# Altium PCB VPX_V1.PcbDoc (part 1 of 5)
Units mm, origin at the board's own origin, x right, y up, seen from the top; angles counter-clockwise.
Board outline 157.76 x 100.08 mm, 10 copper layers (Top Layer (PADS/SIG), Layer 2 (GND), Layer 3 (SIG), Layer 4 (SIG), Layer 5 (GND), Layer 6 (PWR), Layer 7 (GND), Layer 8 (SIG/PWR), Layer 9 (GND), Bottom Layer (PAD/SIG)), stack 1.614 mm thick; 383 components, 223 nets, 1313 pads, 1223 vias.
Unrouted connection lines stored in the file: 3.
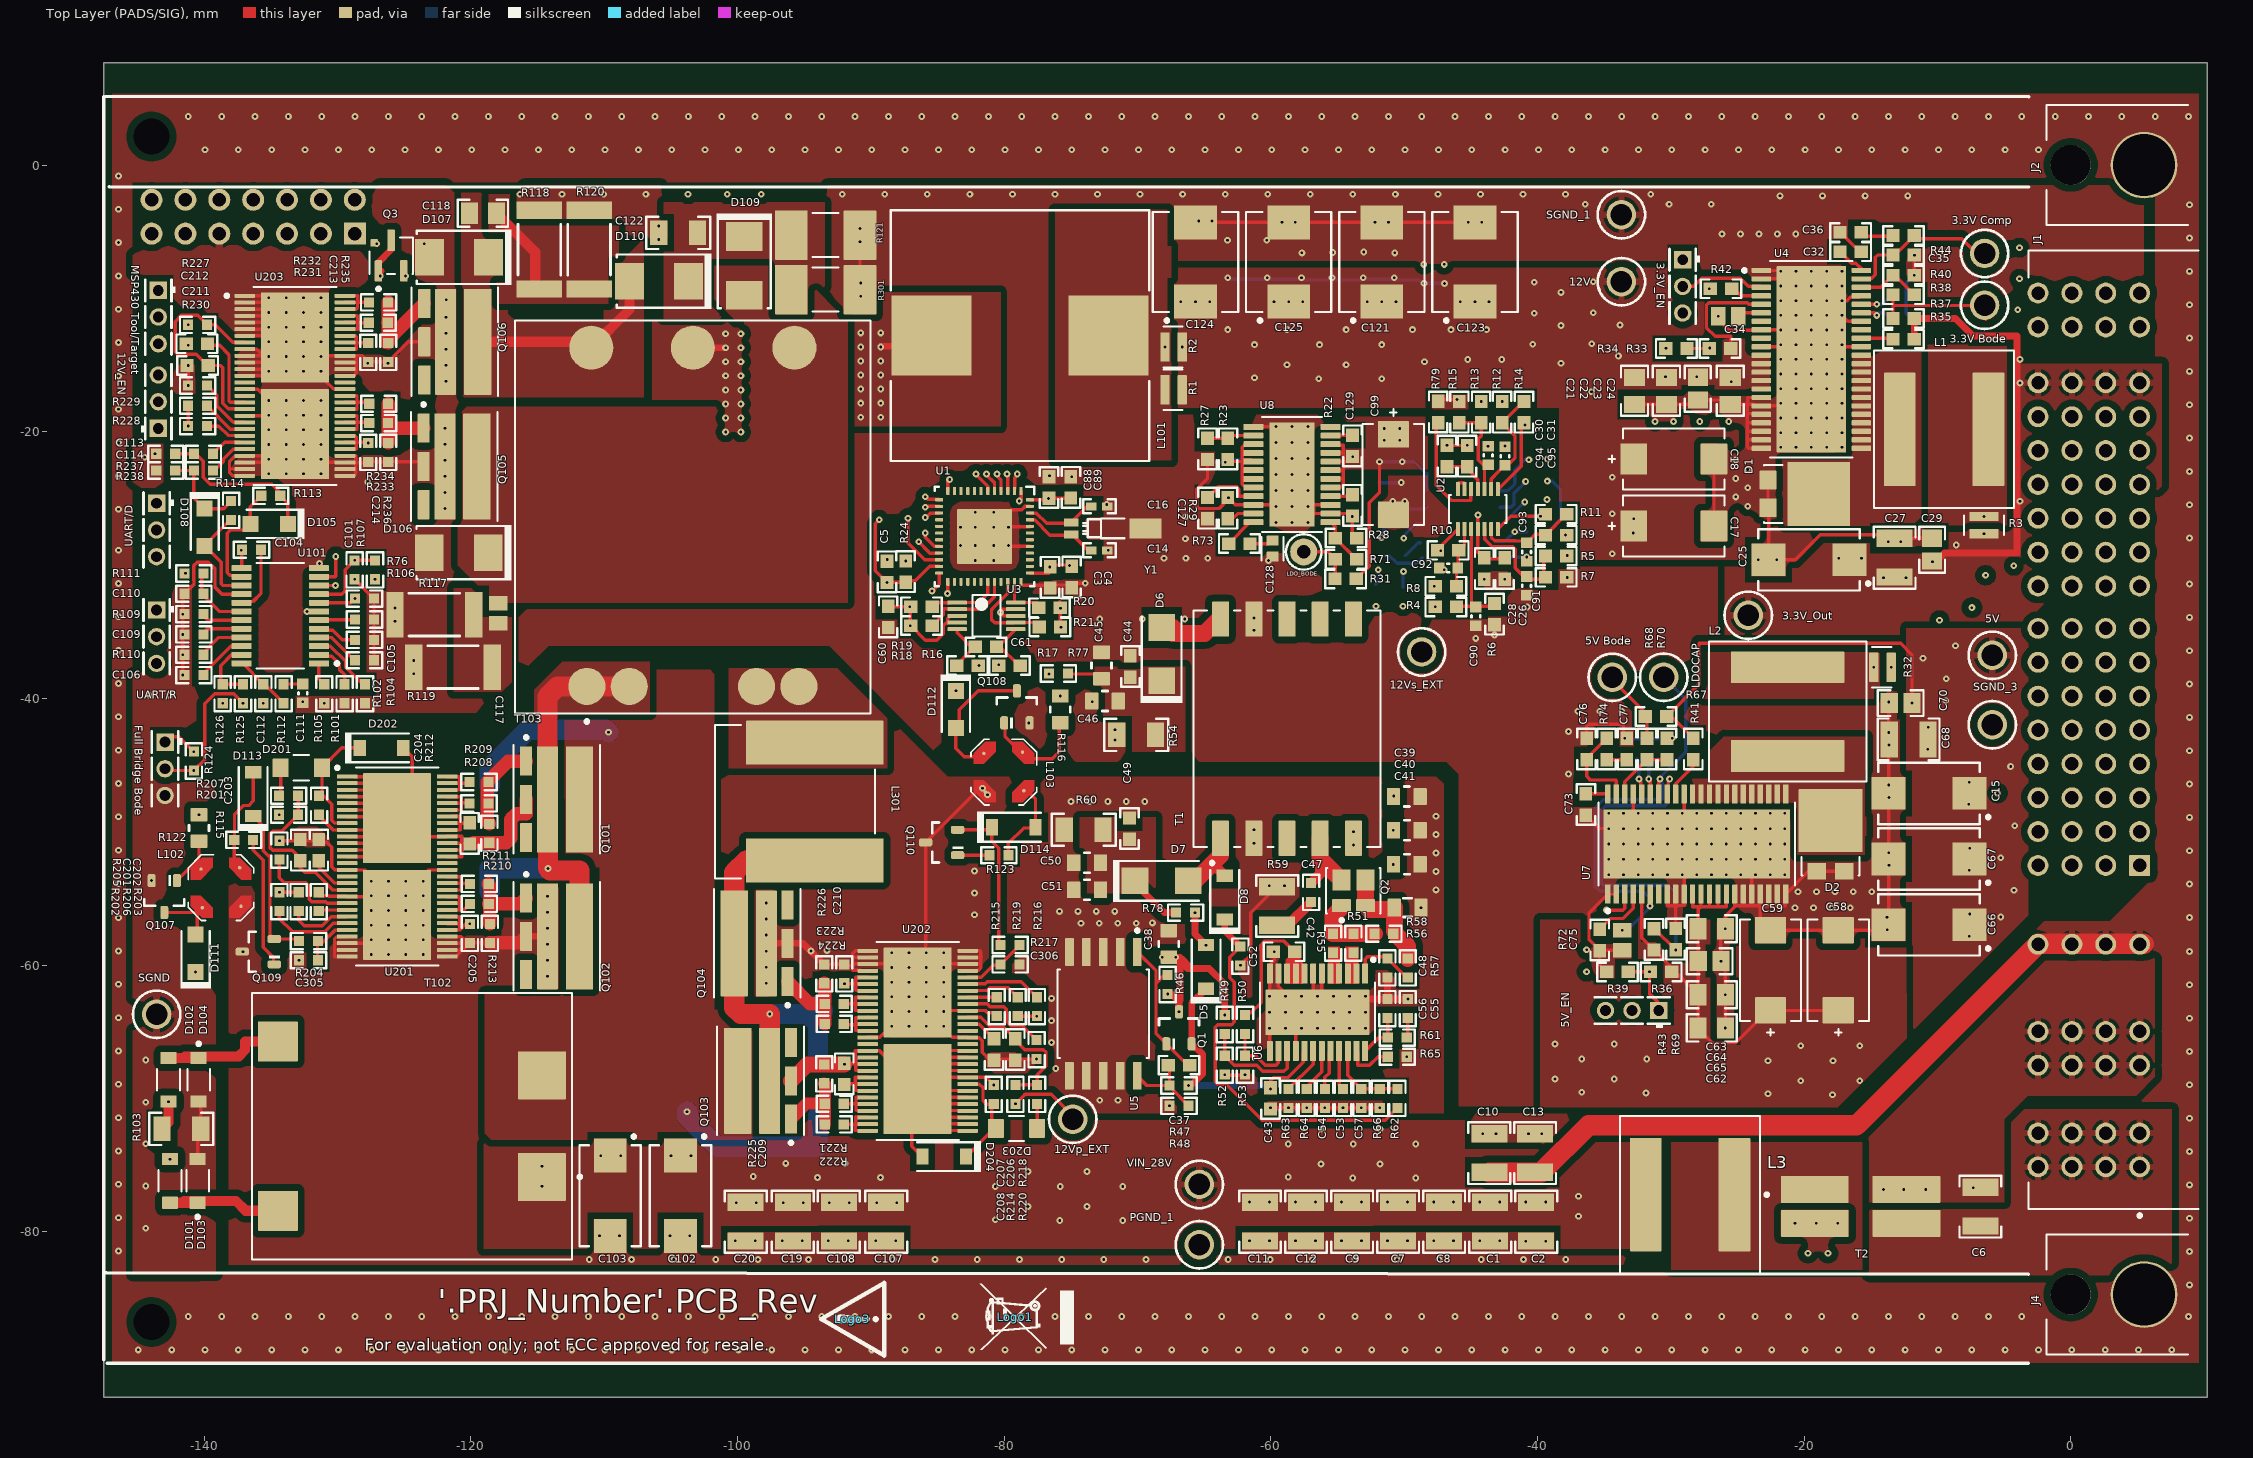
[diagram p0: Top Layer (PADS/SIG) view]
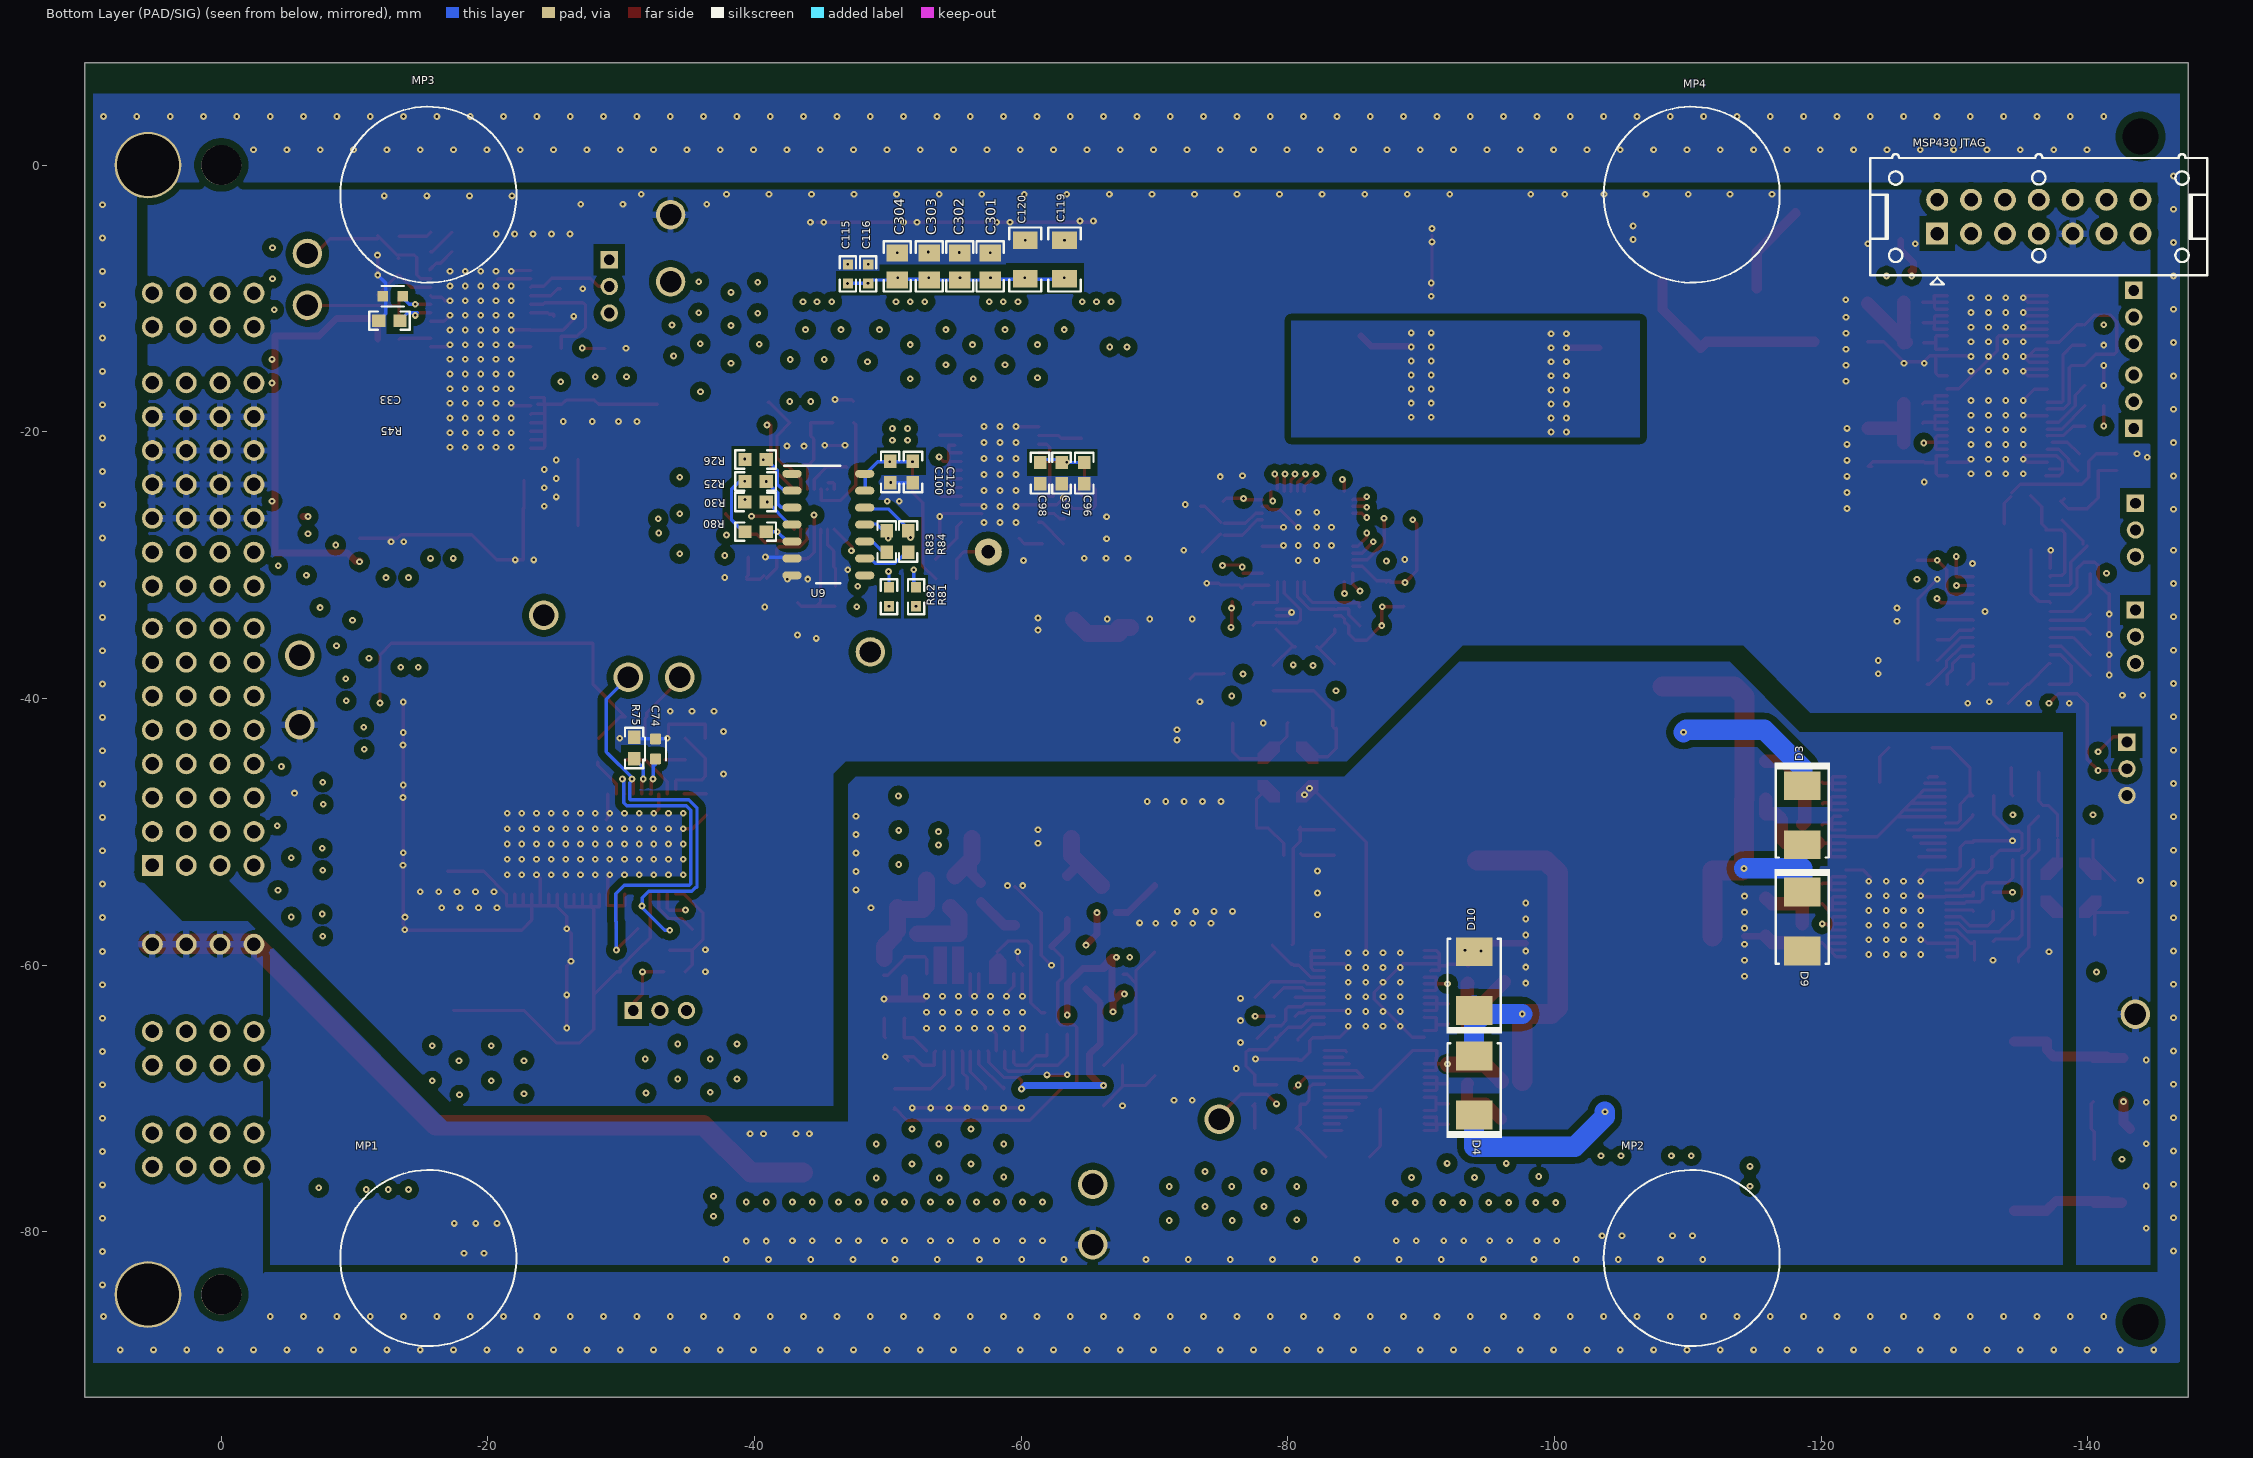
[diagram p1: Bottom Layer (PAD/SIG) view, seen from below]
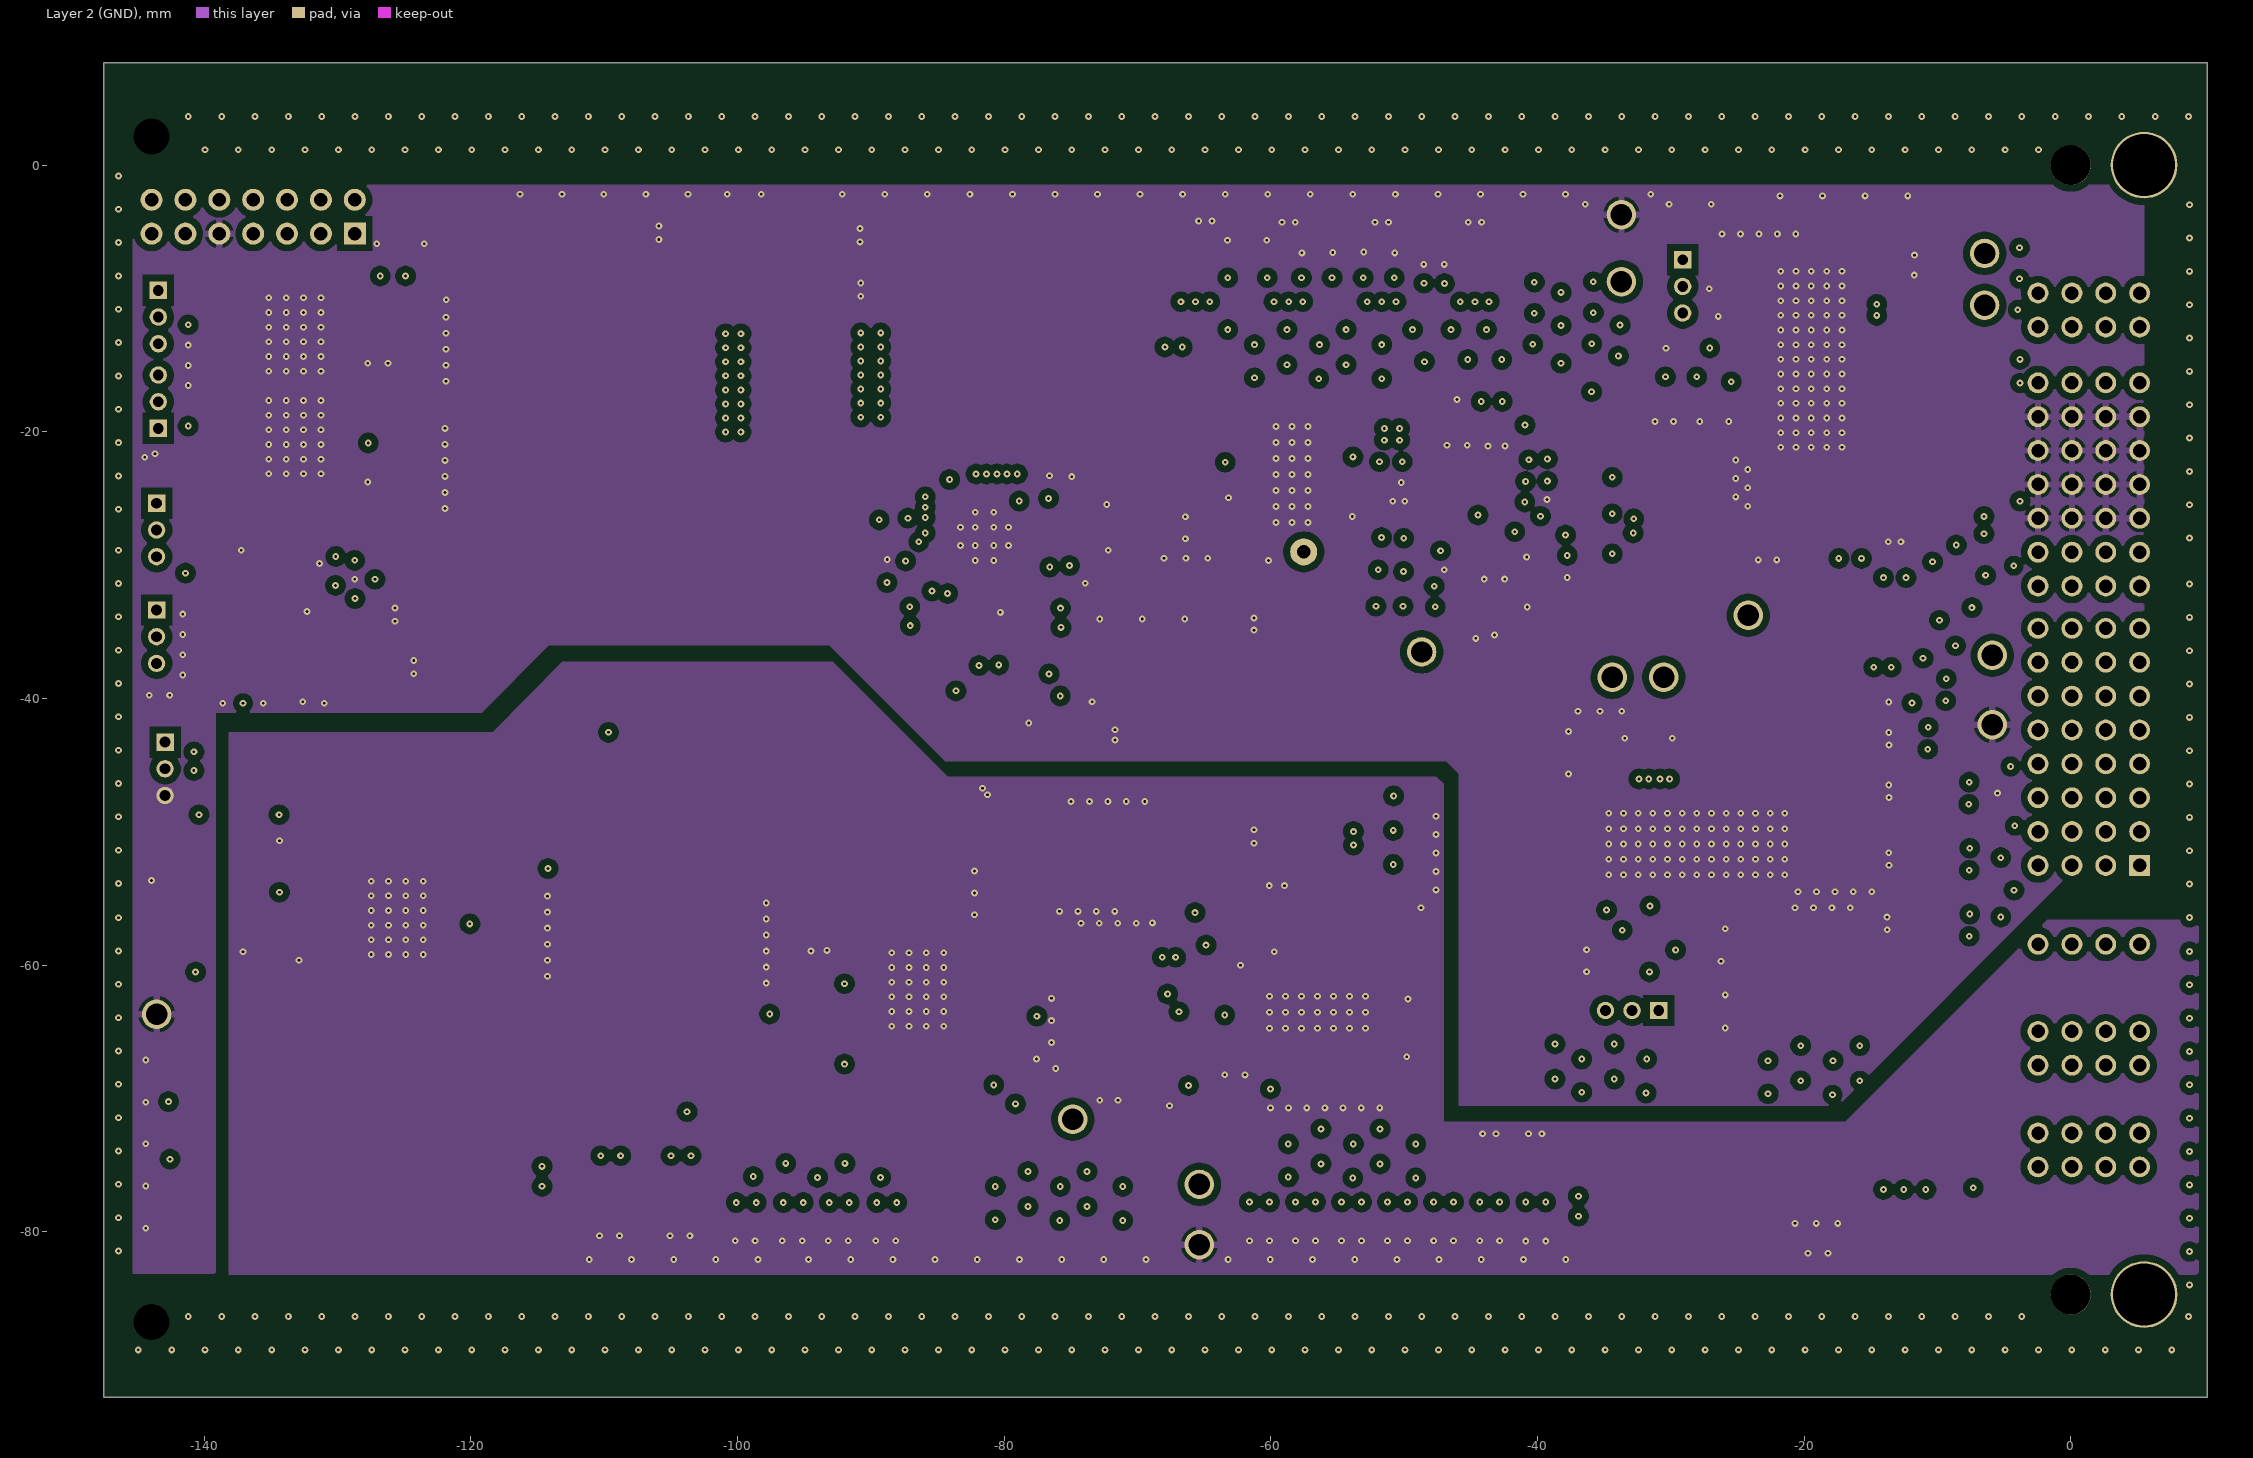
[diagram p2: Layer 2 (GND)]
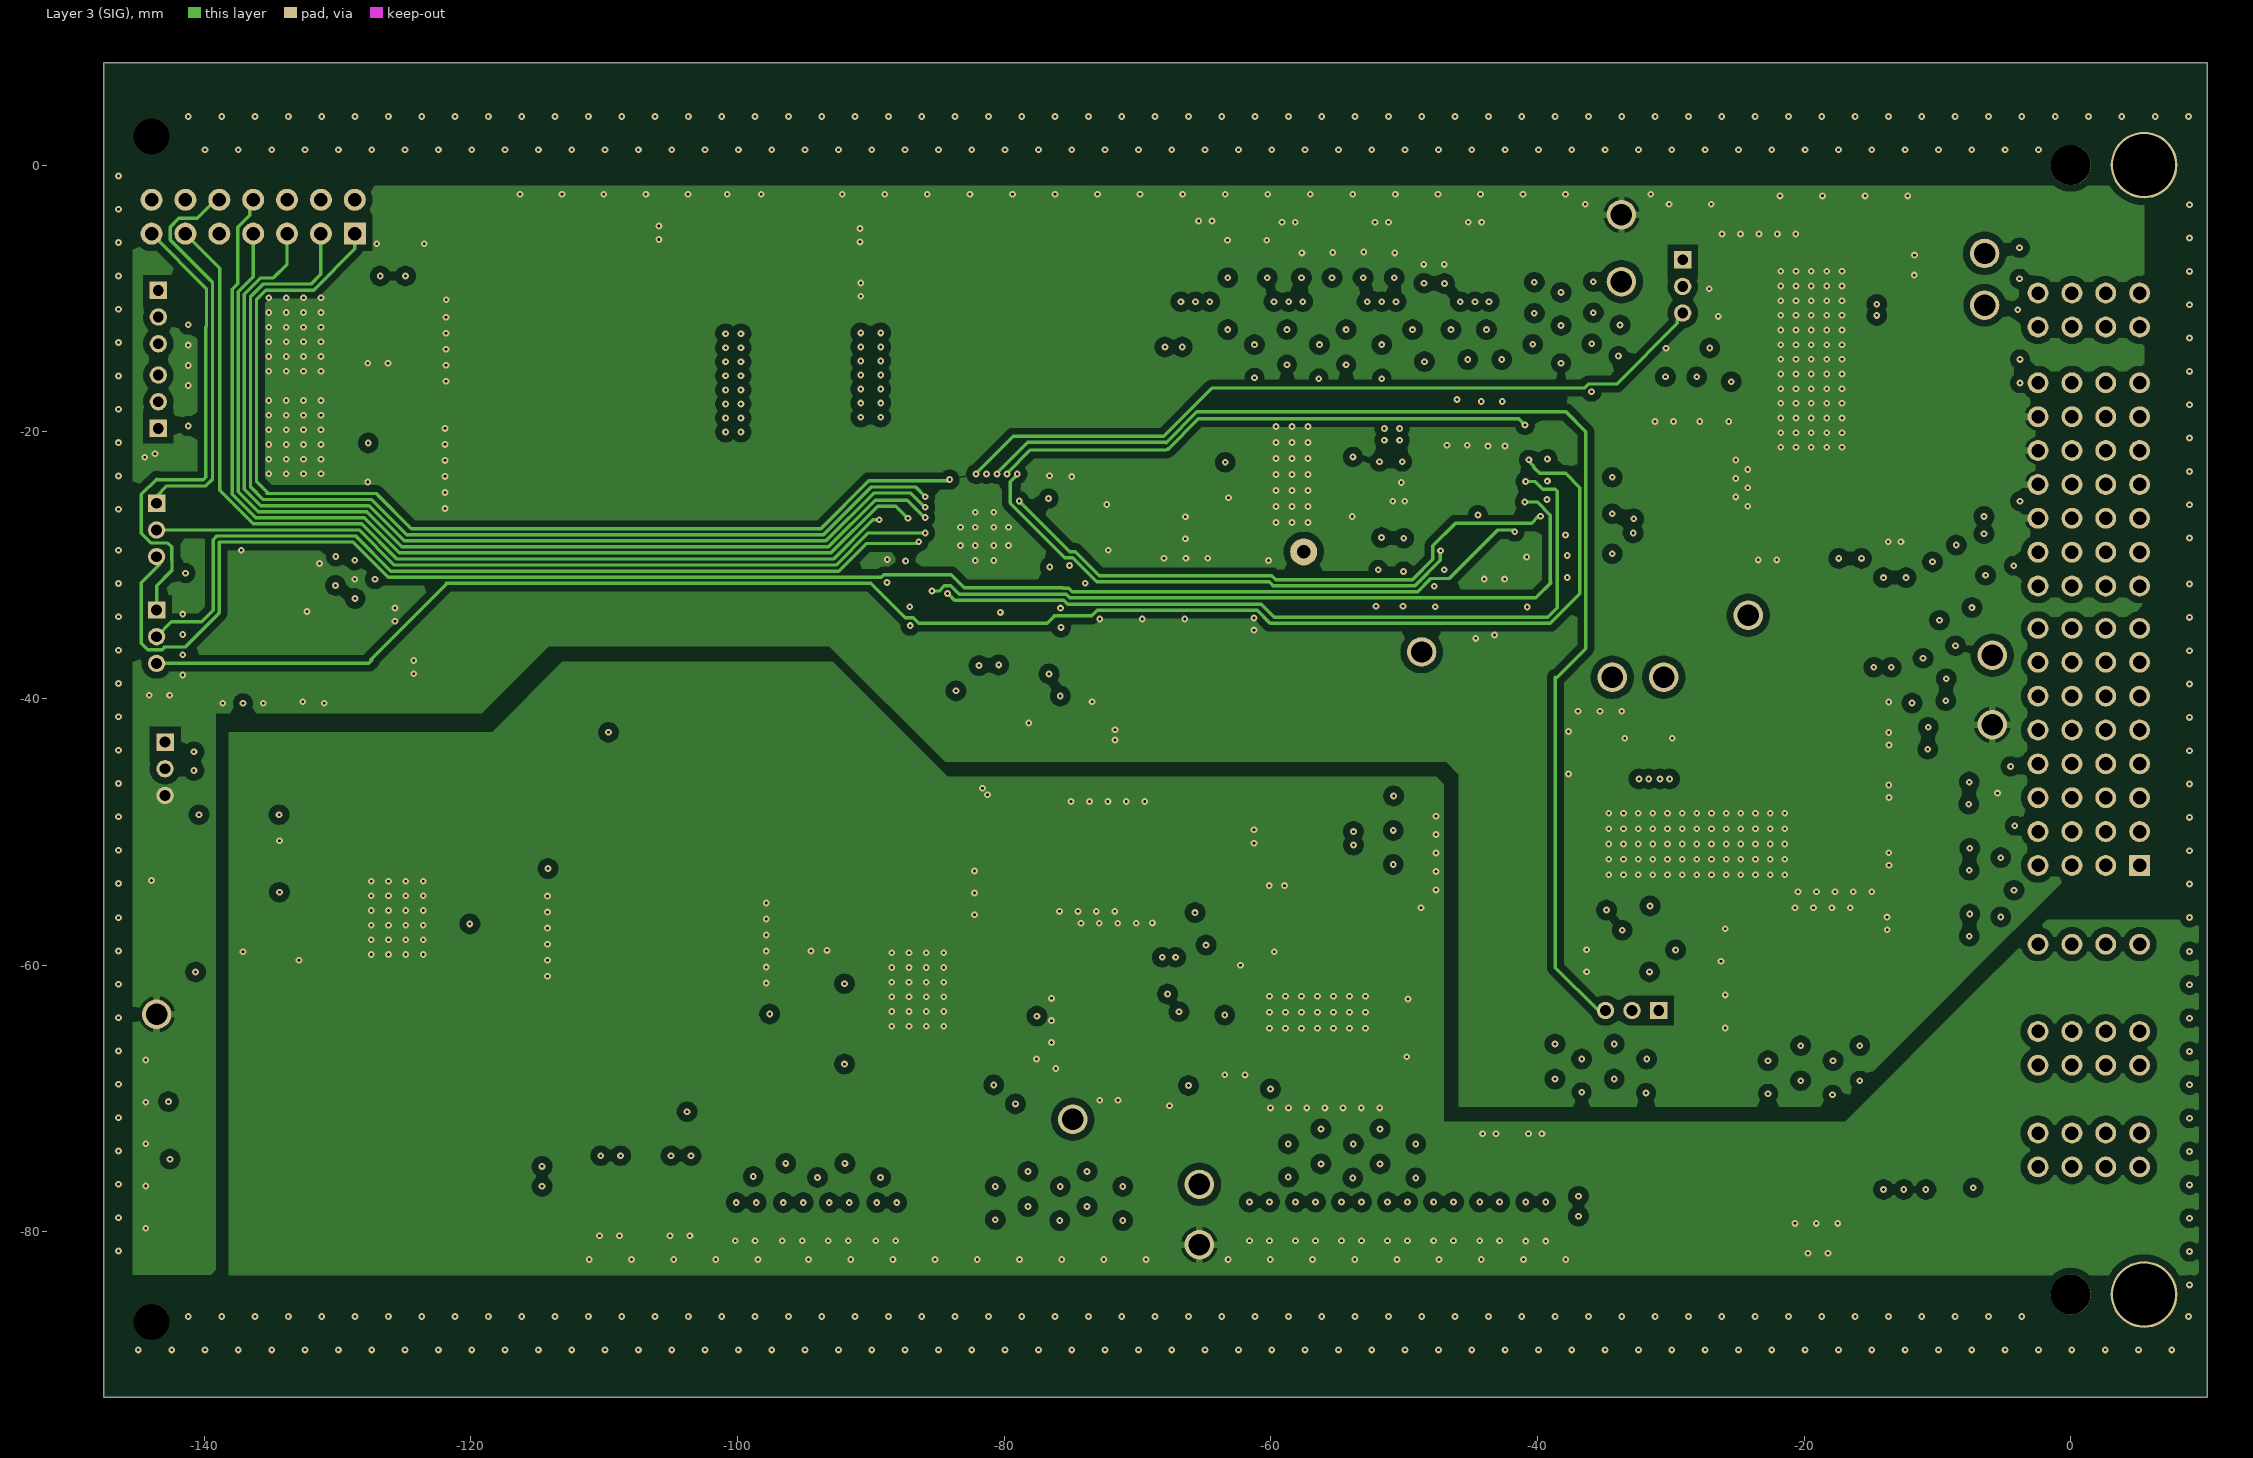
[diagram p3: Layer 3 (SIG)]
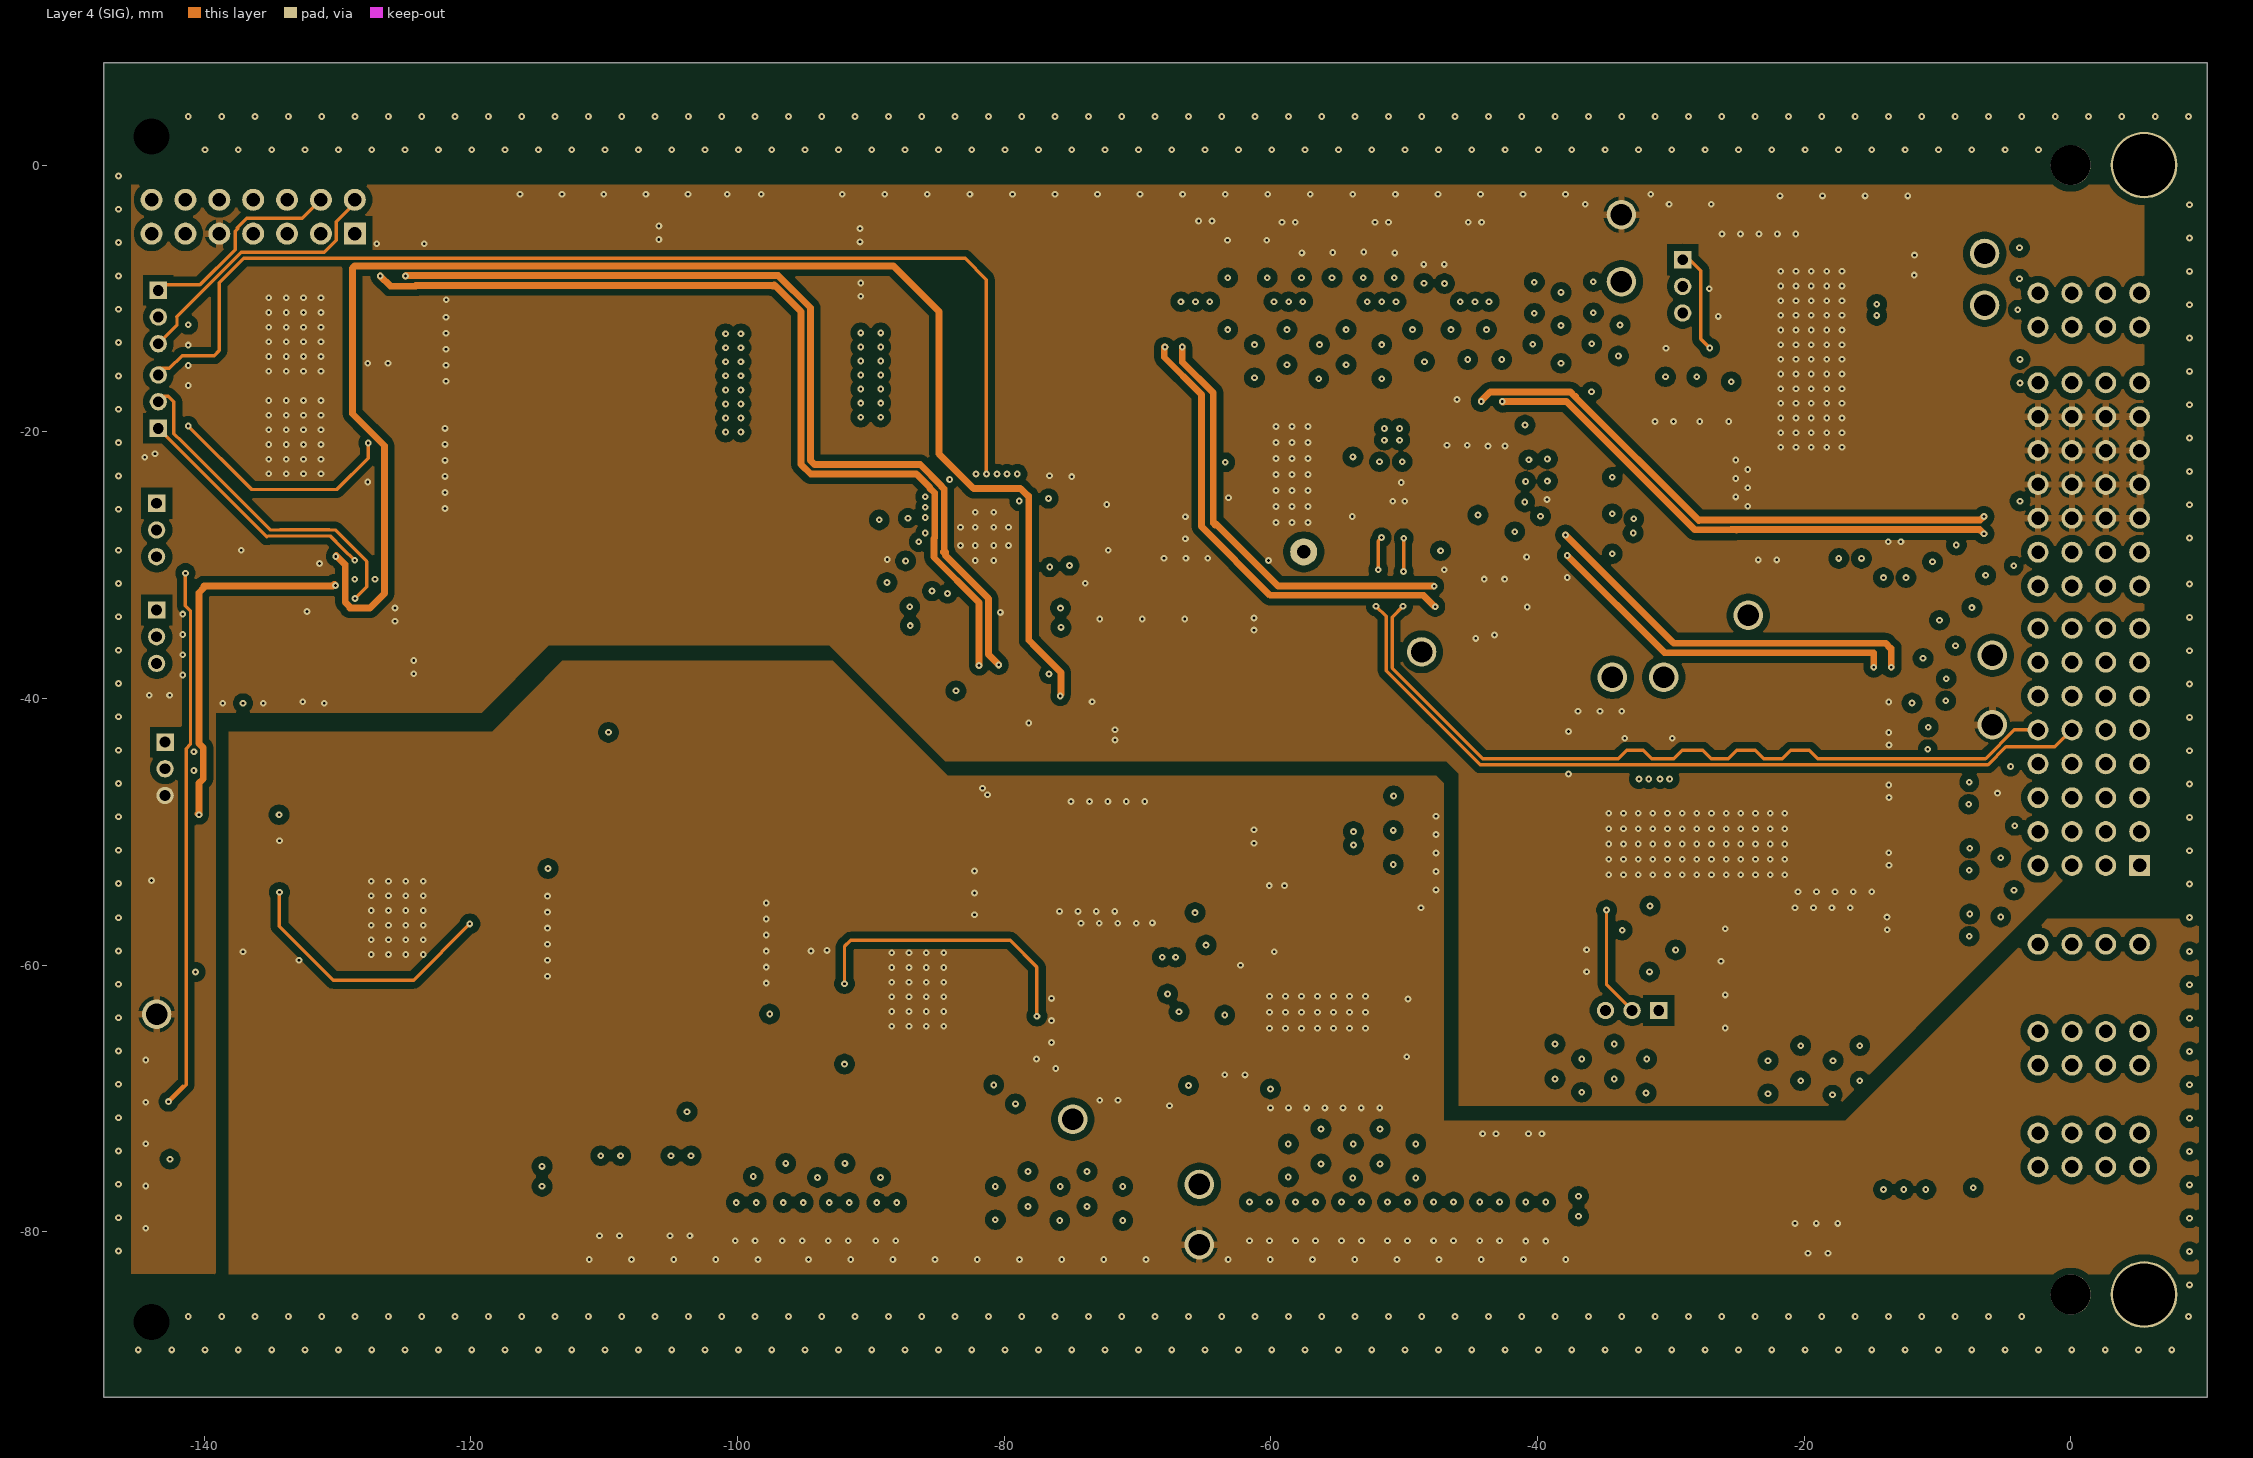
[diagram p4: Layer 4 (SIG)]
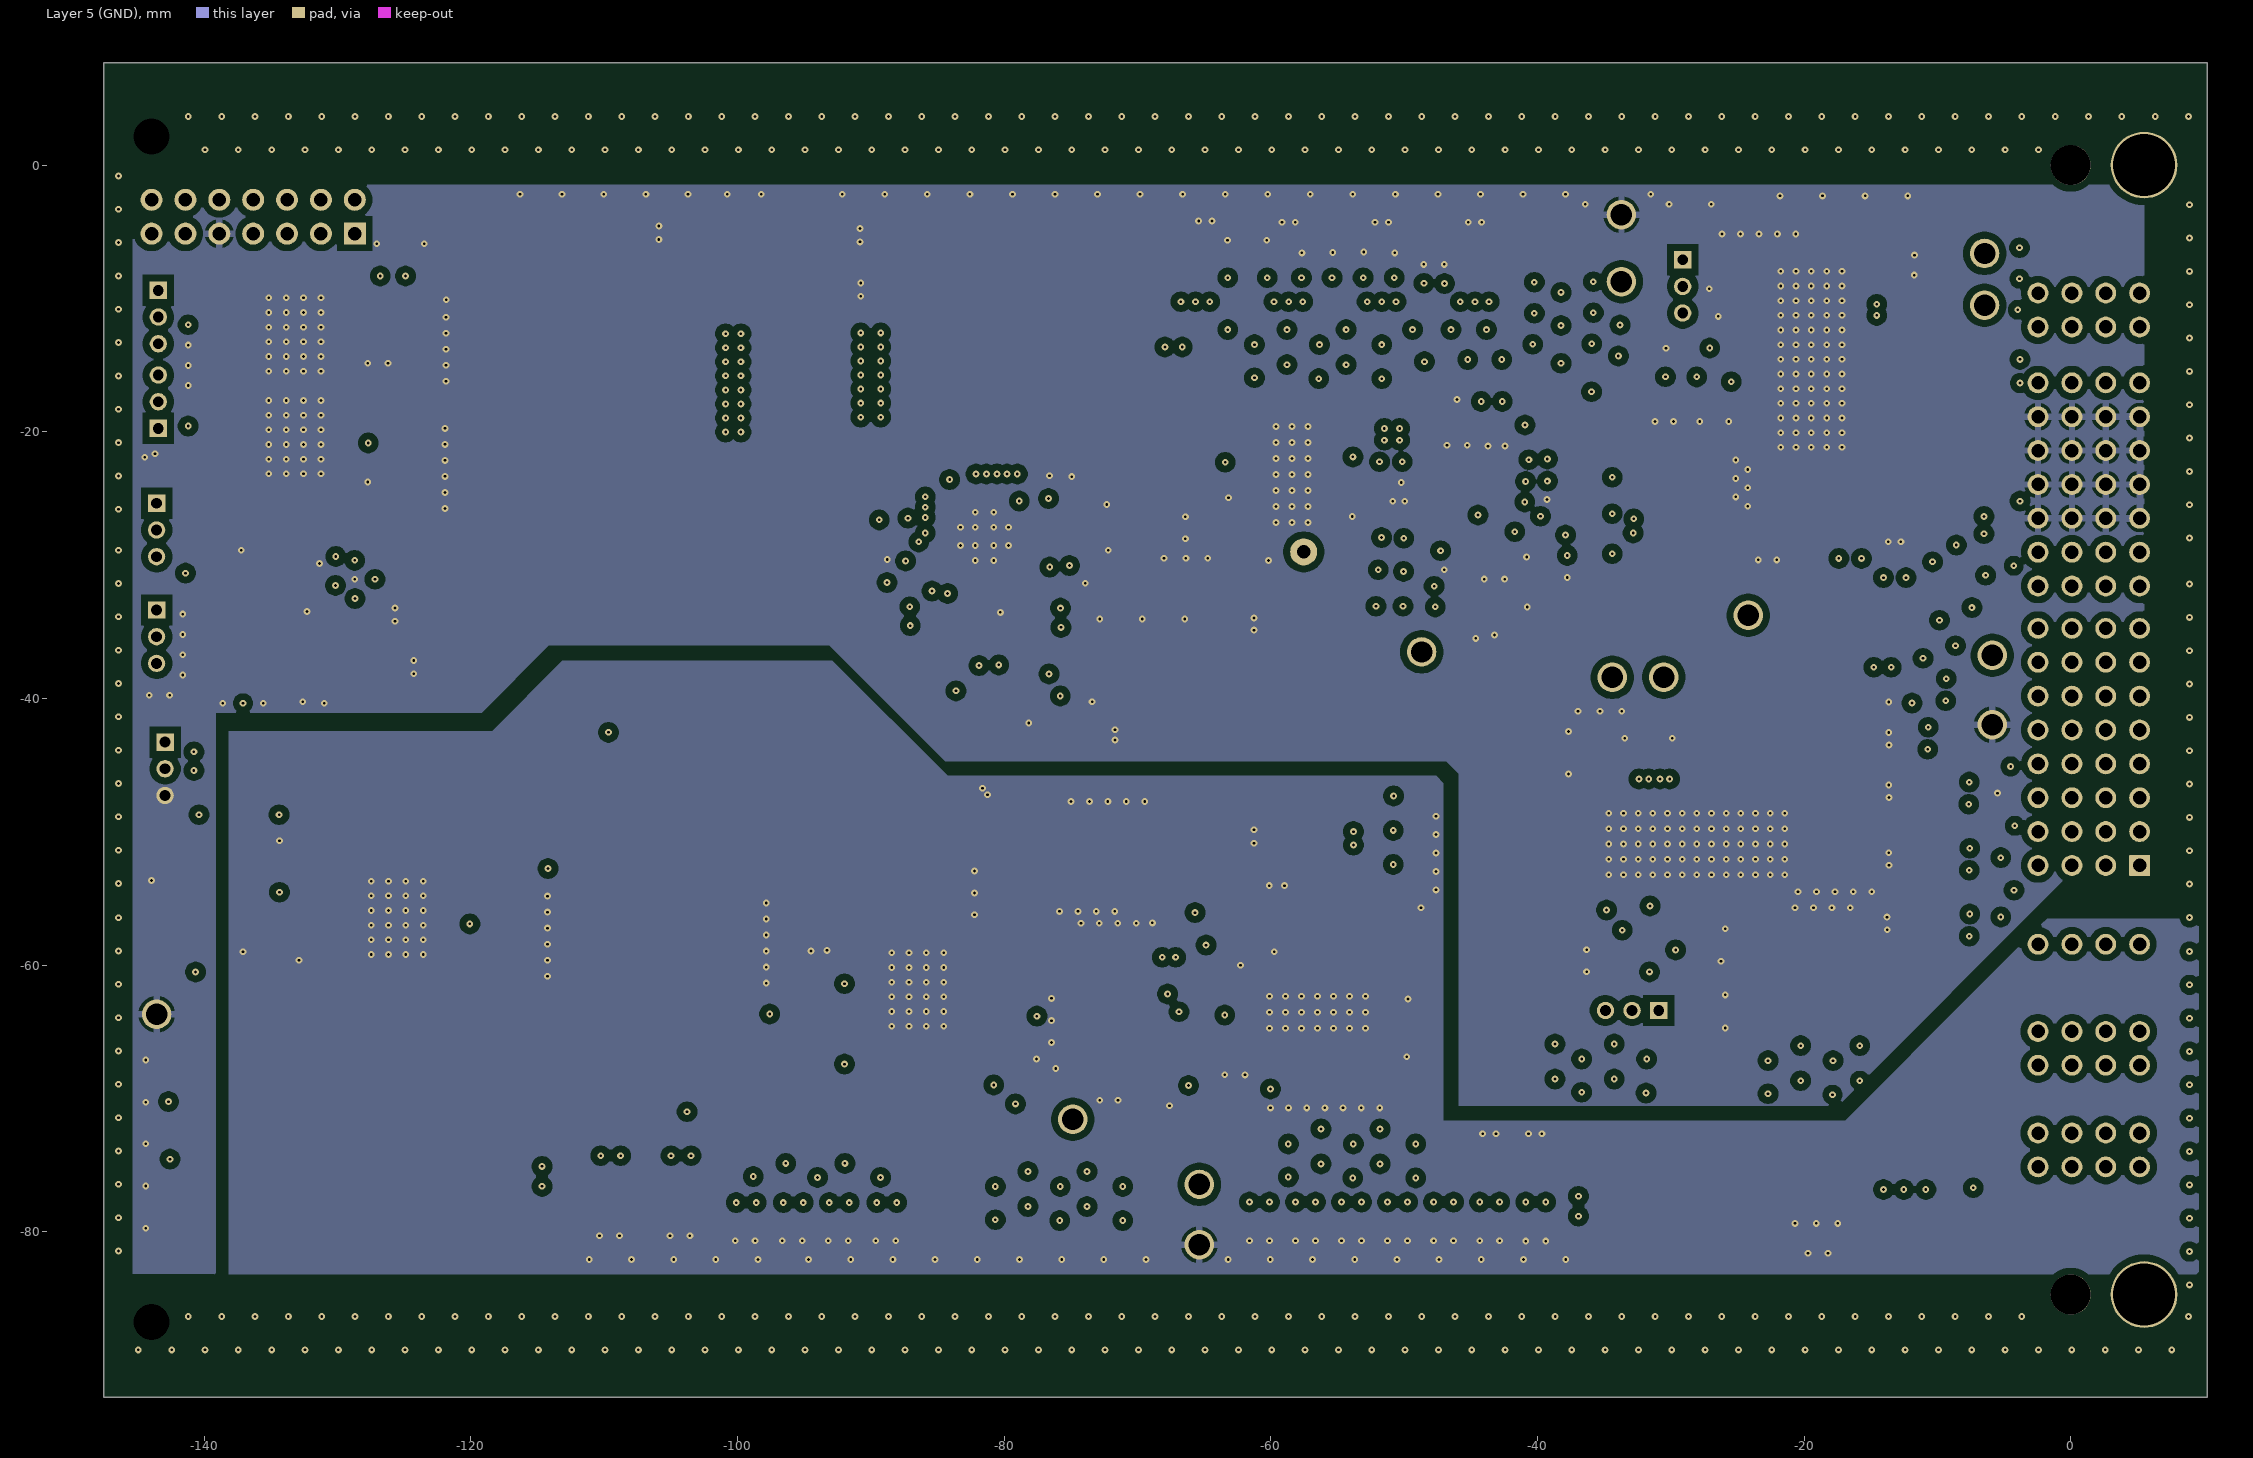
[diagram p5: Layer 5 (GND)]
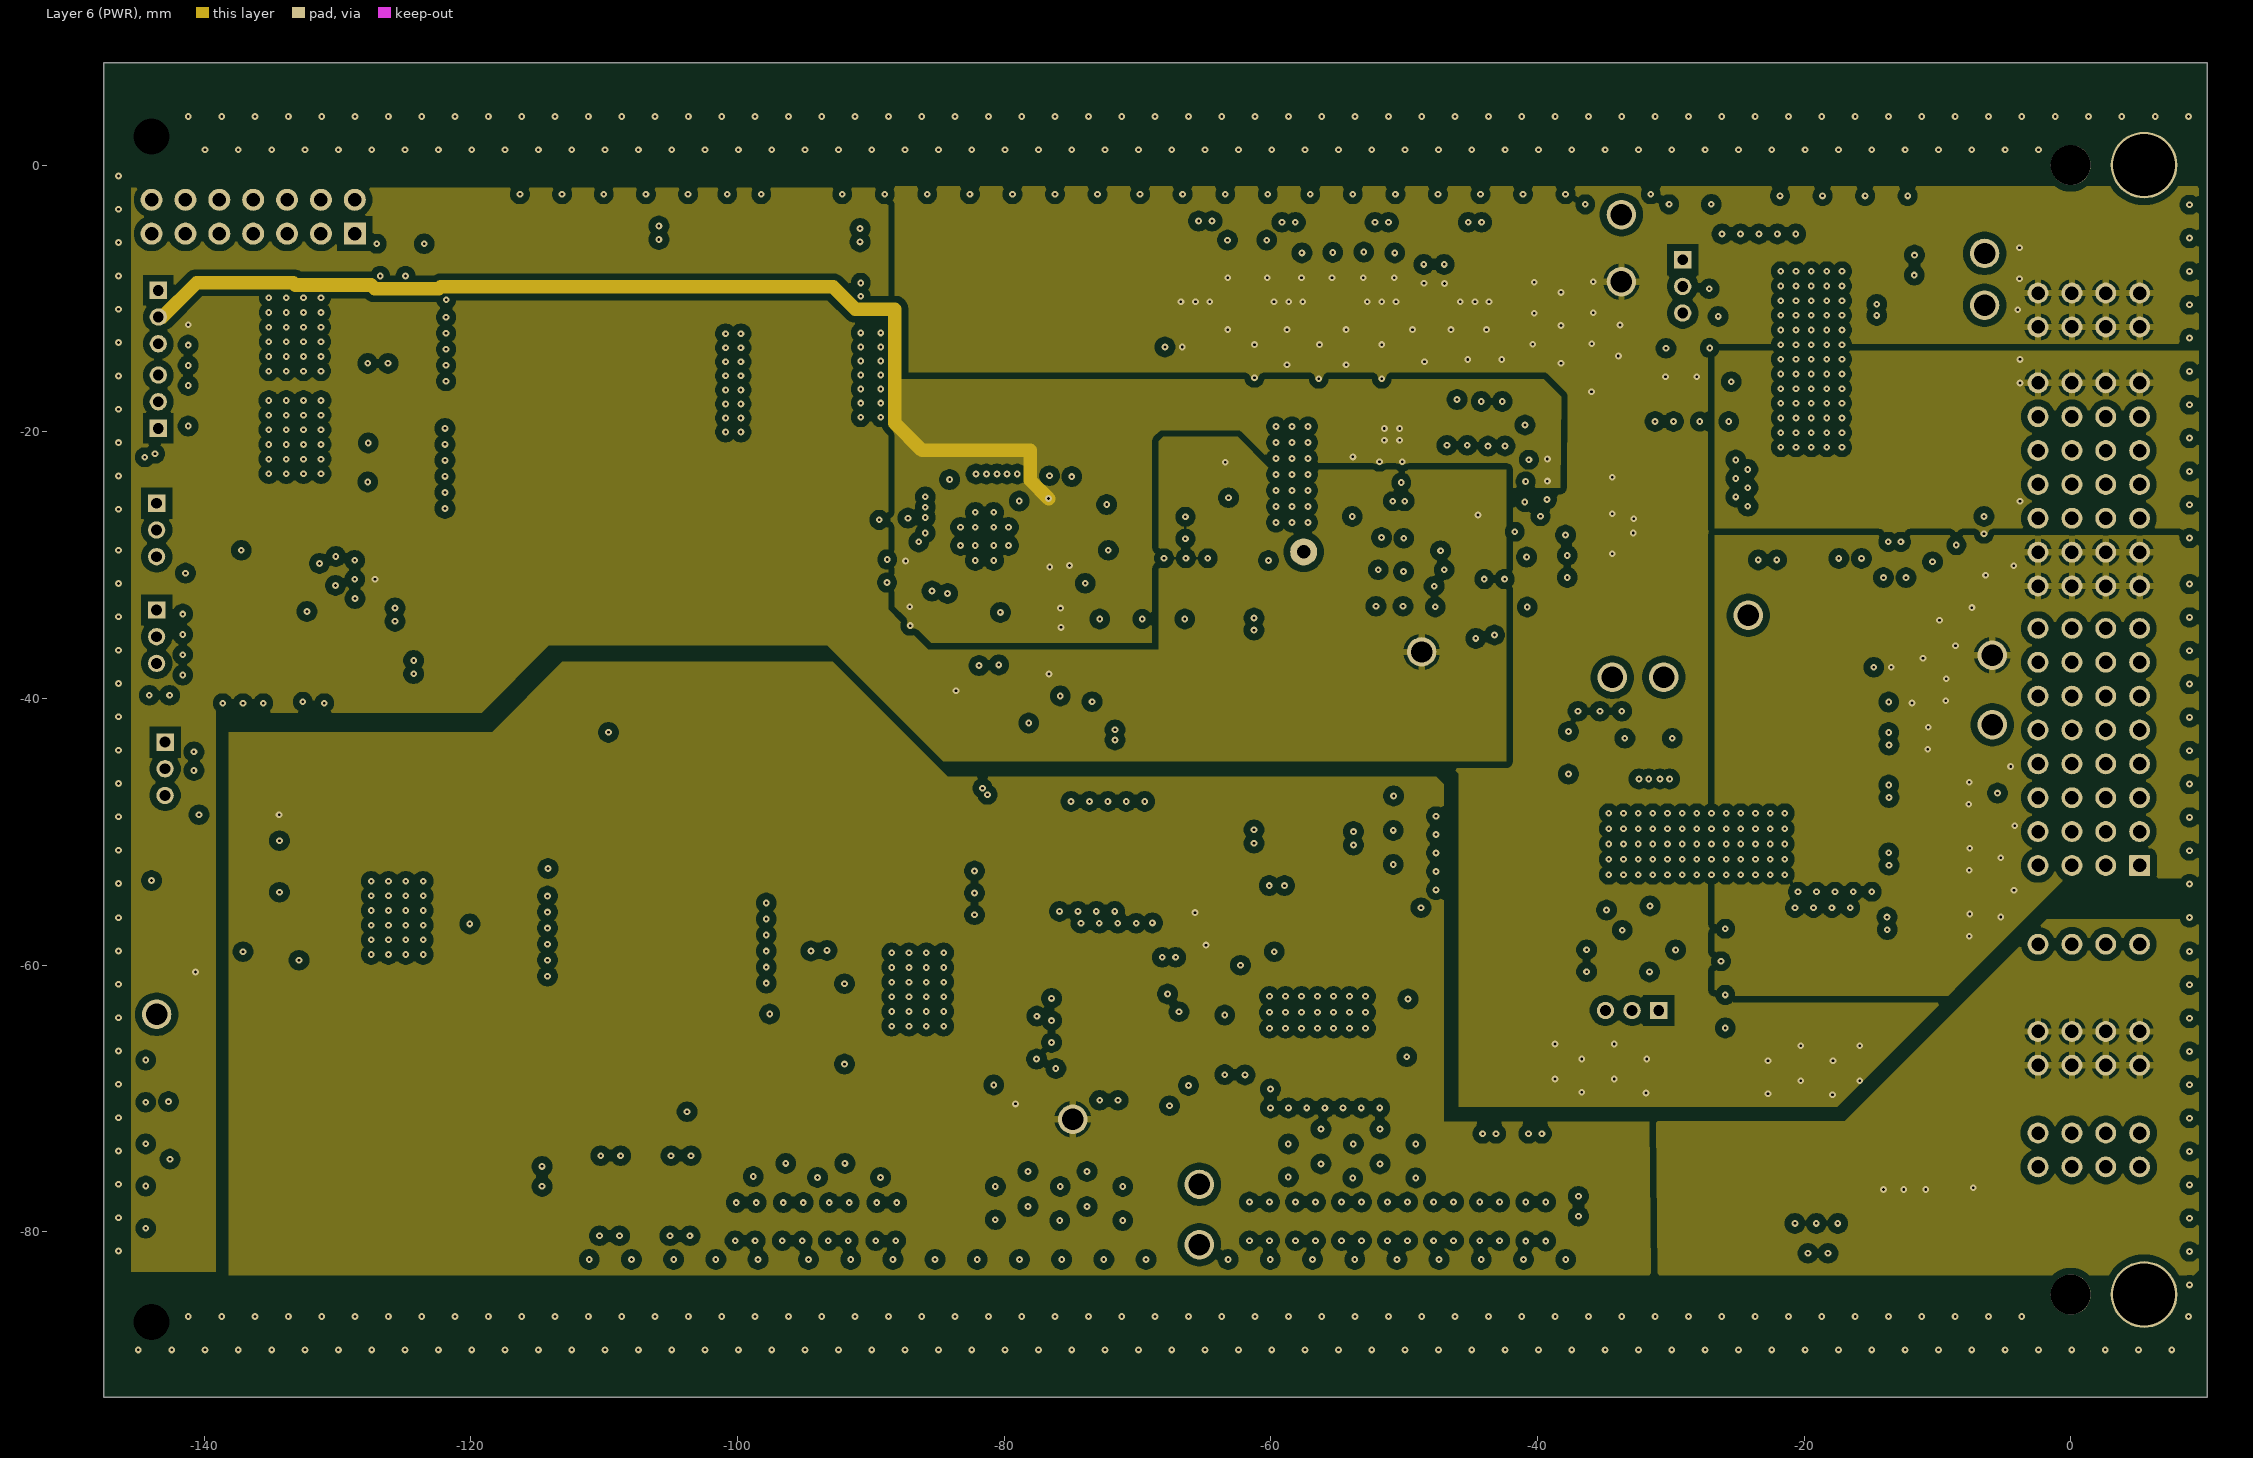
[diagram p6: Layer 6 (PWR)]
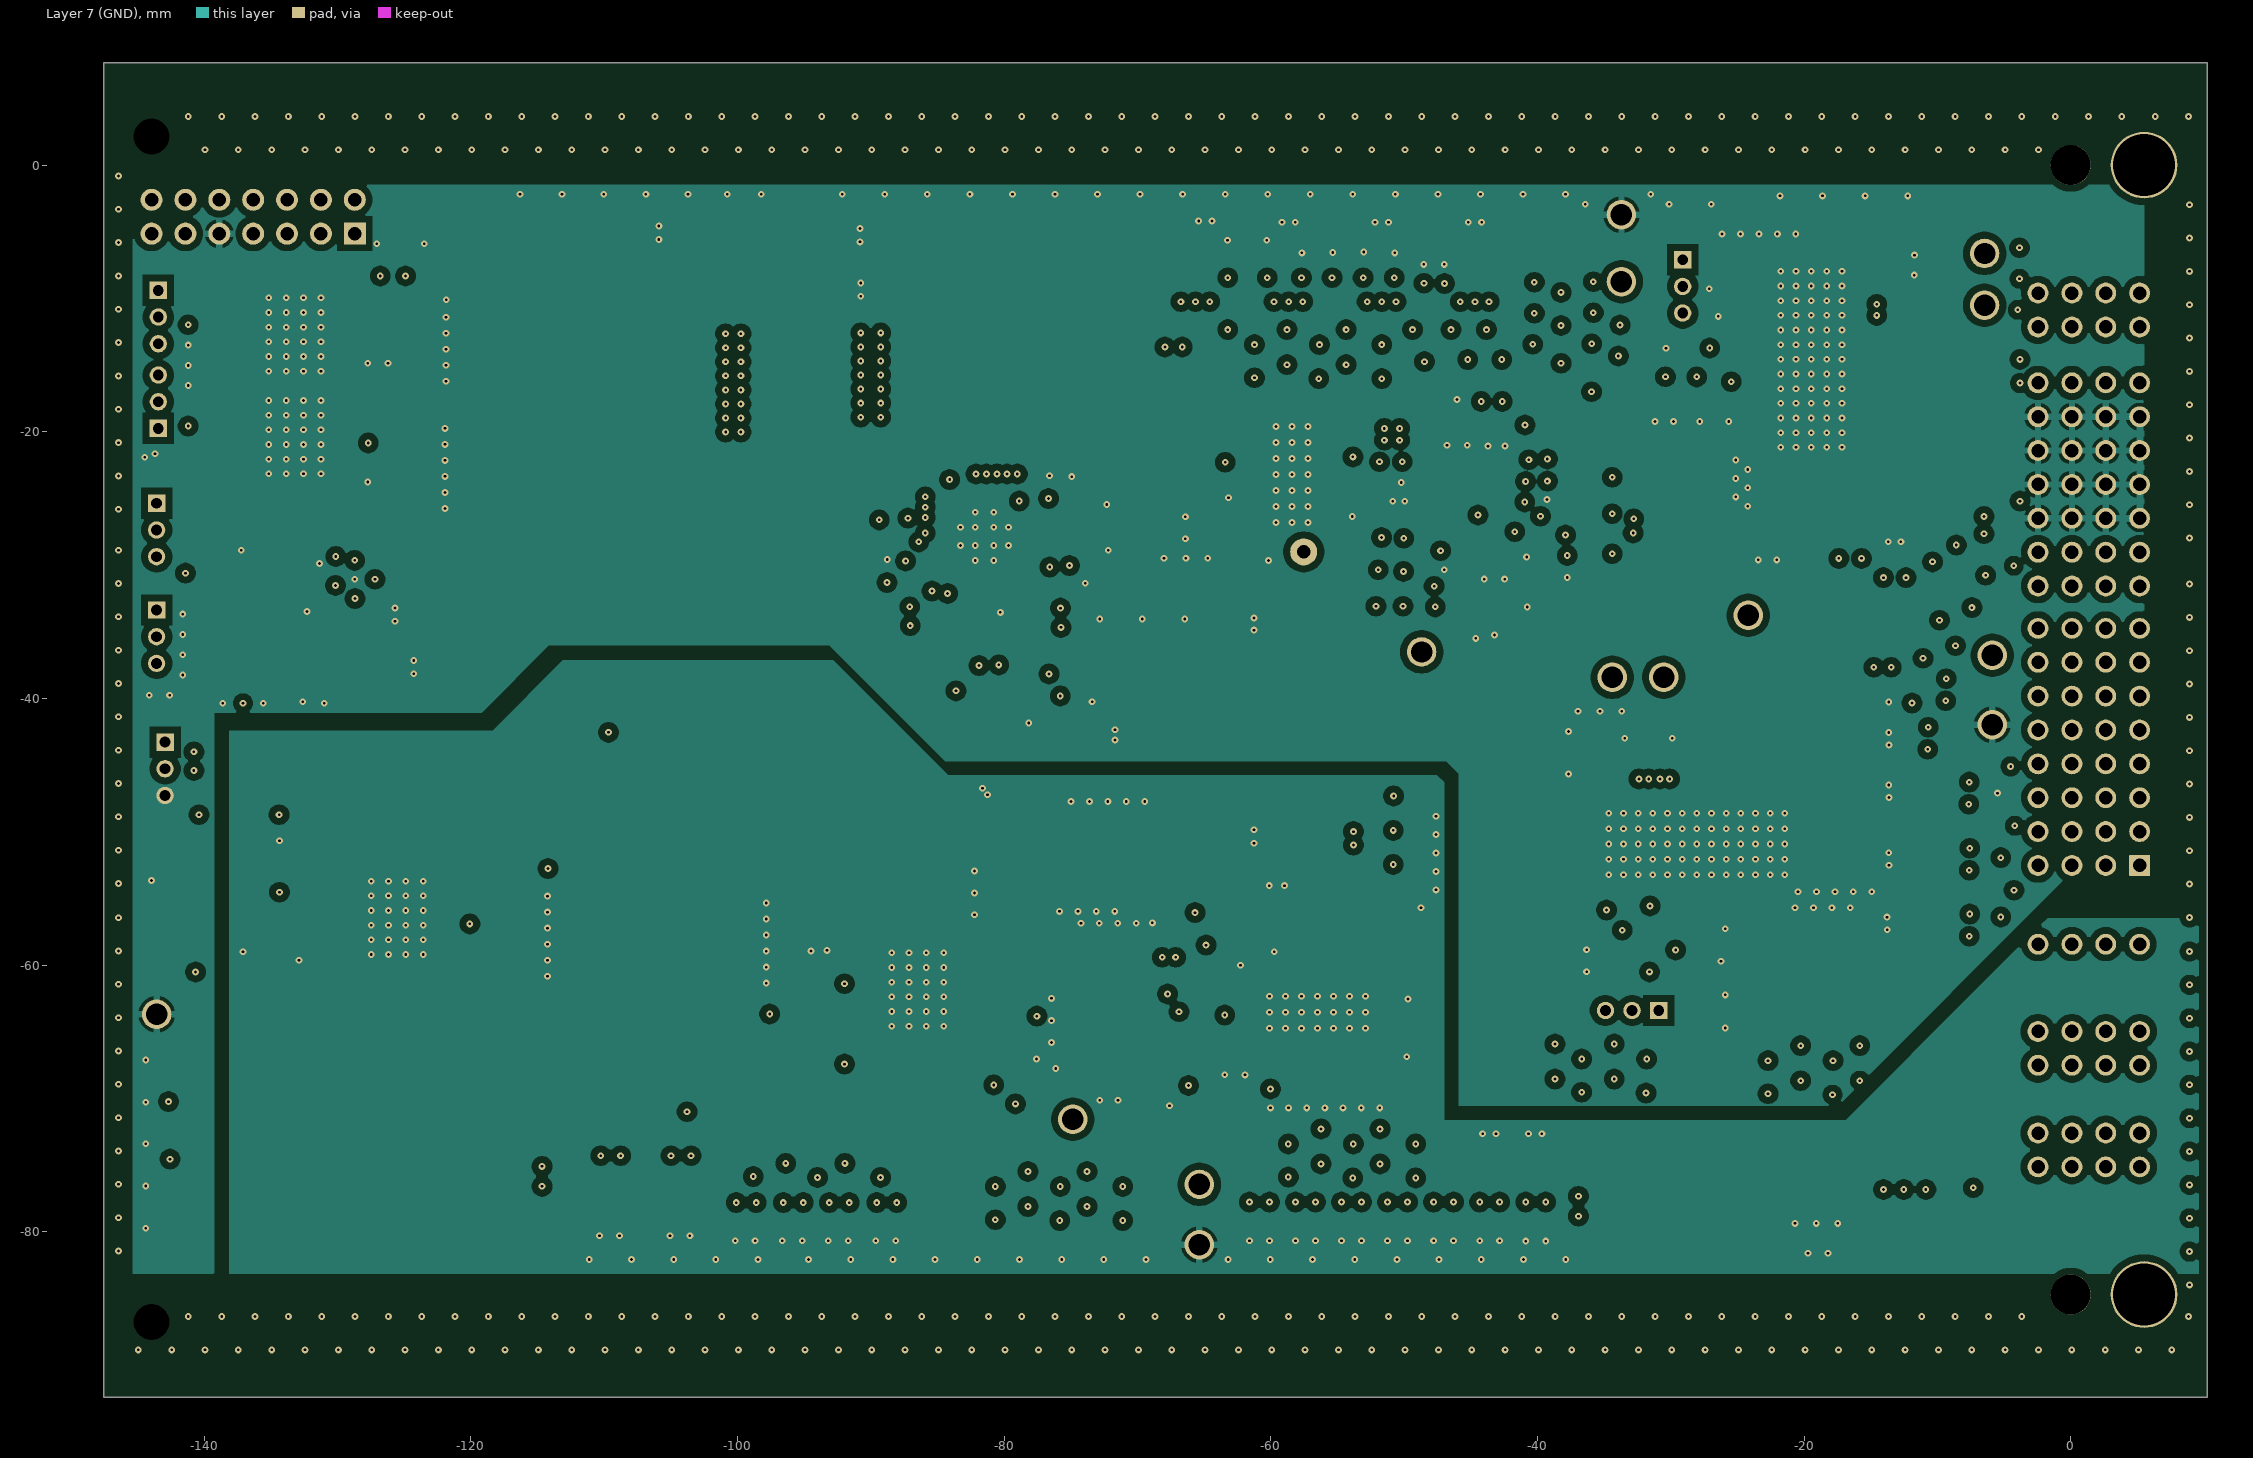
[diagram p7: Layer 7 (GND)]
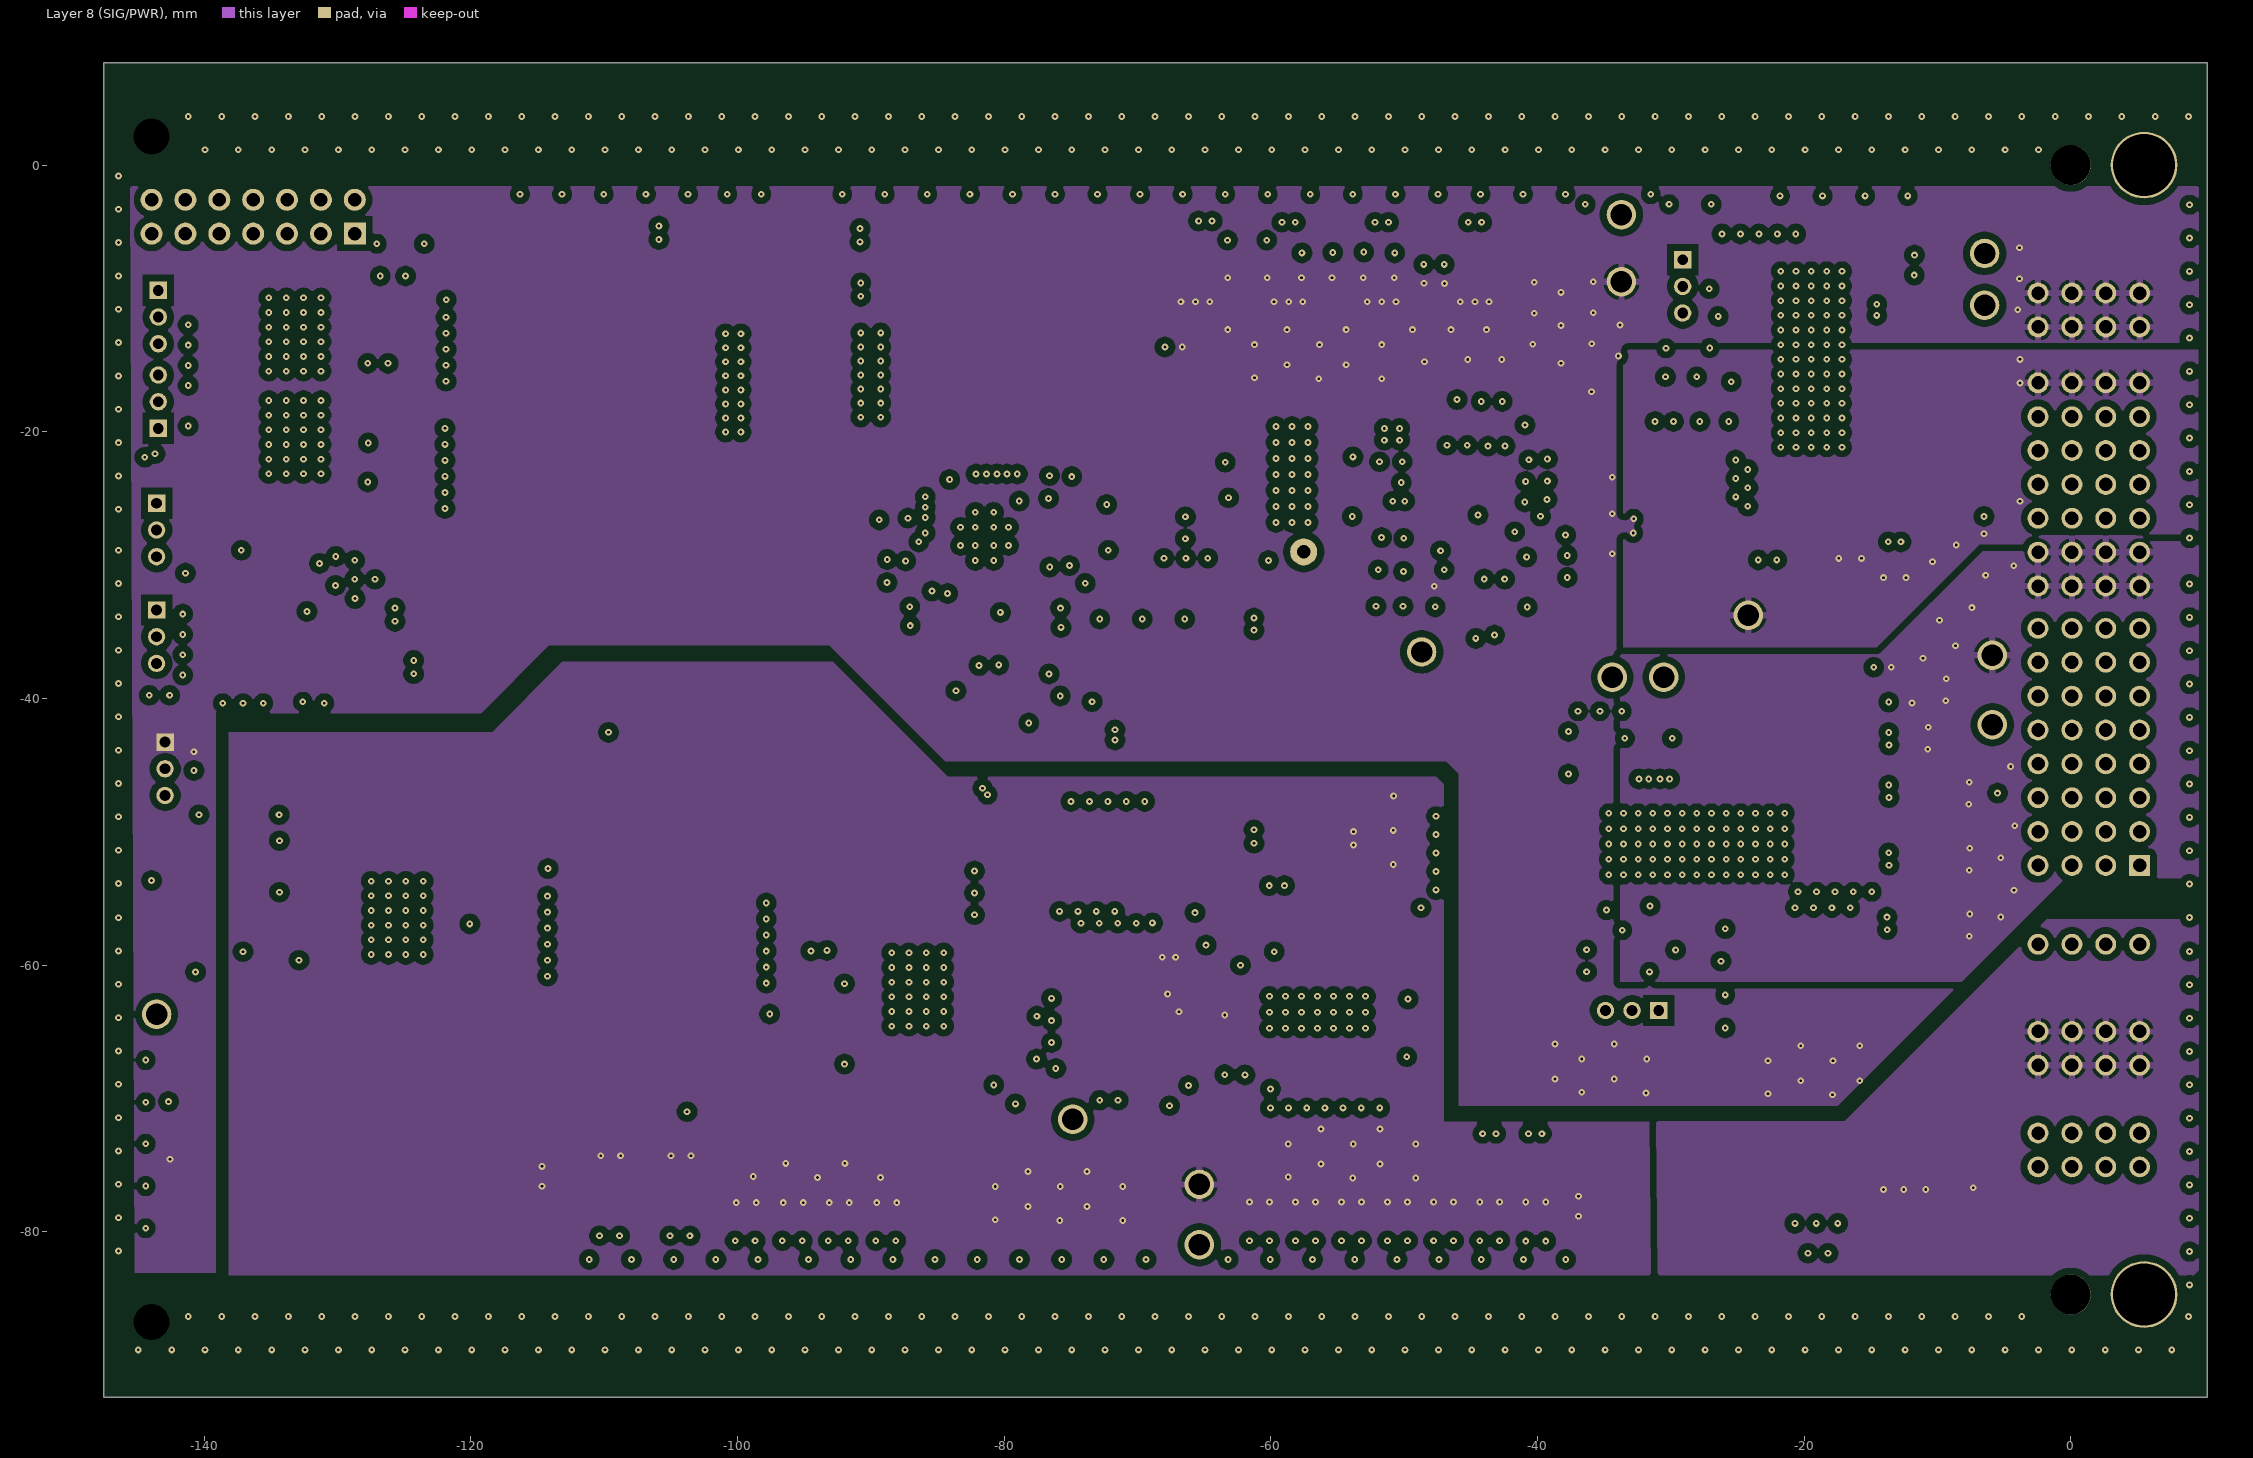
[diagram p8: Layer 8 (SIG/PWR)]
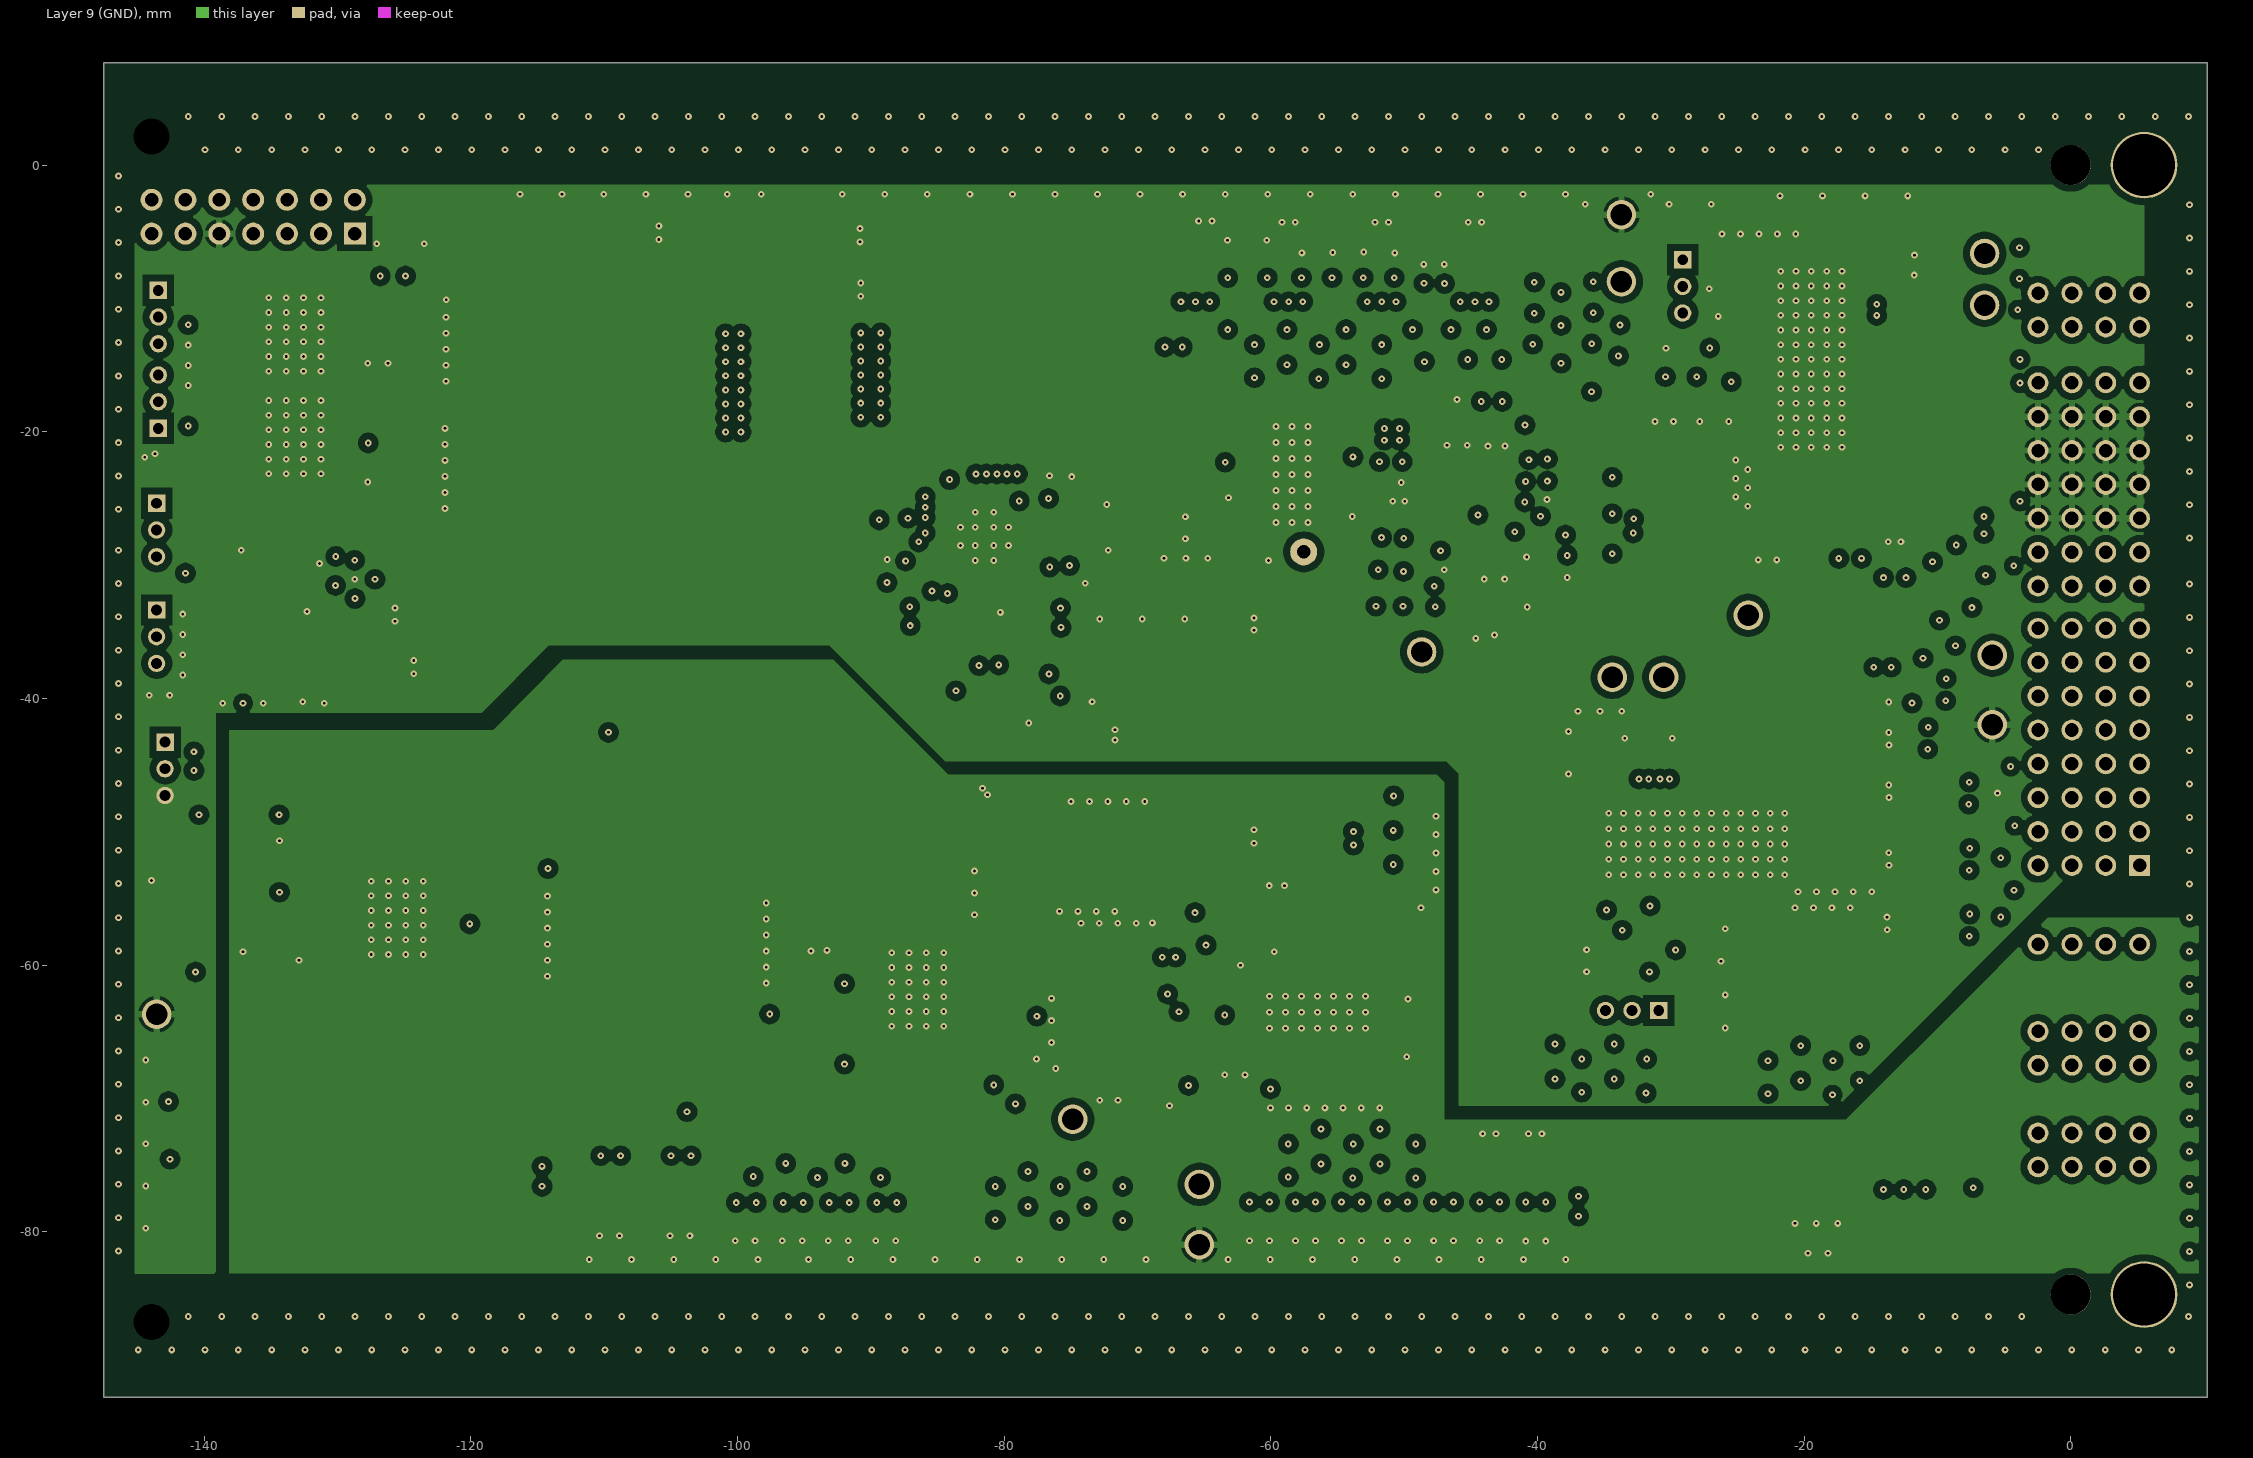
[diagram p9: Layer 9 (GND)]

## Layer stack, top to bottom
Top Solder: solder mask 0.0102, Solder Resist, Dk 3.5
Top Layer (PADS/SIG): signal copper 0.07
Dielectric 1: prepreg 0.1168, PP-016, Dk 4.4
Layer 2 (GND): signal copper 0.035
Dielectric 2: core 0.1524, FR-4 High TG, Dk 4.5
Layer 3 (SIG): signal copper 0.035
Dielectric 3: prepreg 0.1168, PP-016, Dk 4.4
Layer 4 (SIG): signal copper 0.035
Dielectric 4: core 0.1524, FR-4 High TG, Dk 4.5
Layer 5 (GND): signal copper 0.035
Dielectric 5: prepreg 0.1168, PP-016, Dk 4.4
Layer 6 (PWR): signal copper 0.035
Dielectric 6: core 0.1524, FR-4 High TG, Dk 4.5
Layer 7 (GND): signal copper 0.035
Dielectric 7: prepreg 0.1168, PP-016, Dk 4.4
Layer 8 (SIG/PWR): signal copper 0.035
Dielectric 8: core 0.1524, FR-4 High TG, Dk 4.5
Layer 9 (GND): signal copper 0.035
Dielectric 9: prepreg 0.1168, PP-016, Dk 4.4
Bottom Layer (PAD/SIG): signal copper 0.07
Bottom Solder: solder mask 0.0102, Solder Resist, Dk 3.5

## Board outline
-147.511,-92.396 -147.511,7.68 10.244,7.68 10.244,-92.396

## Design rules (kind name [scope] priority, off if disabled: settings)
AcuteAngle [All] p1: minimum=4.50000000000000E+0001 checktracksonly=TRUE
AssemblyTestPointUsage [All] p1: valid=2
BoardOutlineClearance BoardOutlineClearance_MountingHoles [OnCopper and InComponentClass('Mounting Holes')] p1: gap=0.635 ignorepadtopadclearanceinfootprint=FALSE
BoardOutlineClearance BoardOutlineClearance_Poly [OnCopper and InPoly] p2: gap=0.635 ignorepadtopadclearanceinfootprint=FALSE
BoardOutlineClearance [OnCopper and Not InComponentClass('Logo') and not InComponentClass('FiducialMark') and not InRegion(1000,500,4000,800)] p3: gap=0.635 ignorepadtopadclearanceinfootprint=FALSE
Clearance Clearance_2 [InNetClass('HV') vs Not InNetClass('HV')] p1: gap=1.524 ignorepadtopadclearanceinfootprint=FALSE
Clearance Clearance_1 [InNetClass('MV') vs Not InNetClass('MV')] p2: gap=0.762 ignorepadtopadclearanceinfootprint=FALSE
Clearance Clearance_Keepouts [((IsTrack Or IsArc) And Not InPoly) And IsFree and IsKeepOut vs ((IsTrack Or IsArc) And Not InPoly) And IsFree and IsKeepOut] p3: gap=0 ignorepadtopadclearanceinfootprint=FALSE
Clearance Clearance_BoardEdge_MountingHoles [OnCopper and InComponentClass('Mounting Holes') vs IsKeepOut] p4: gap=1.016 ignorepadtopadclearanceinfootprint=FALSE except(0: Arc-Hole Track-Hole SMDPad-Hole THPad-Hole Via-Hole Fill-Hole Poly-Hole Region-Hole Text-Hole)
Clearance Clearance_BoardEdge_Poly [OnCopper and InPoly vs IsKeepOut] p5: gap=1.27 ignorepadtopadclearanceinfootprint=FALSE except(0: Arc-Hole Track-Hole SMDPad-Hole THPad-Hole Via-Hole Fill-Hole Poly-Hole Region-Hole Text-Hole)
Clearance Clearance_BoardEdge [OnCopper and Not InComponentClass('Logo') and not InComponentClass('FiducialMark') and not InRegion(1000,500,4000,800) and Not IsKeepout vs IsKeepOut] p6: gap=1.27 ignorepadtopadclearanceinfootprint=FALSE
Clearance Clearance_Poly [InPolygon] p7: gap=0.508 ignorepadtopadclearanceinfootprint=FALSE except(0: Arc-Hole Track-Hole SMDPad-Hole THPad-Hole Via-Hole Fill-Hole Poly-Hole Region-Hole Text-Hole)
Clearance [All] p8: gap=0.2 ignorepadtopadclearanceinfootprint=FALSE except(0: Arc-Hole Track-Hole SMDPad-Hole THPad-Hole Via-Hole Fill-Hole Poly-Hole Region-Hole Text-Hole)
ComponentClearance [InComponent('T101') vs InComponent('T102')] p1: gap=0 collisioncheckmode=3 verticalgap=2540 showdistances=TRUE
ComponentClearance ComponentClearance_2 [All] p2: gap=0.254 collisioncheckmode=3 verticalgap=0.254 showdistances=FALSE
ComponentClearance ComponentClearance_1 [InComponent('T101')] p3: gap=0 collisioncheckmode=3 verticalgap=0 showdistances=FALSE
ComponentClearance ComponentClearance_MountingHoles_FiducialMarks [InComponentClass('Mounting Holes') vs InComponentClass('FiducialMark')] p4: gap=0.508 collisioncheckmode=3 verticalgap=0.254 showdistances=FALSE
ComponentClearance ComponentClearance_Shunt [InComponentClass('Header') vs InComponentClass('Shunt')] p5: gap=0 collisioncheckmode=3 verticalgap=0 showdistances=FALSE
ComponentClearance ComponentClearance_Logo [InComponentClass('Logo')] p6: gap=0.127 collisioncheckmode=3 verticalgap=0.254 showdistances=FALSE
ComponentClearance ComponentClearance_ScrewToNut [(HasFootprint('NY PMS 440 0025 PH')) vs (HasFootprint('Keystone_1902C'))] p7: gap=0.508 collisioncheckmode=3 verticalgap=2540 showdistances=FALSE
ComponentClearance ComponentClearance_MountingHoles [InComponentClass('Mounting Holes')] p8: gap=0.508 collisioncheckmode=3 verticalgap=0.254 showdistances=FALSE
ComponentClearance ComponentClearance_SmallPassives [HasFootprint('0201*') or HasFootprint('0402*') or HasFootprint('0508') or HasFootprint('0603*') or HasFootprint('0612') or HasFootprint('0805*') or HasFootprint('0815*') or HasFootprint('0830*') or HasFootprint('1206*') or HasFootprint('1210*') or HasFootprint('1808*') or HasFootprint('1812*') or HasFootprint('1825*') or HasFootprint('2010*') or HasFootprint('2220*') or HasFootprint('2225*') or HasFootprint('2512*') or HasFootprint('2728*') or HasFootprint('3518*') vs HasFootprint('0201*') or HasFootprint('0402*') or HasFootprint('0508') or HasFootprint('0603*') or HasFootprint('0612') or HasFootprint('0805*') or HasFootprint('0815*') or HasFootprint('0830*') or HasFootprint('1206*') or HasFootprint('1210*') or HasFootprint('1808*') or HasFootprint('1812*') or HasFootprint('1825*') or HasFootprint('2010*') or HasFootprint('2220*') or HasFootprint('2225*') or HasFootprint('2512*') or HasFootprint('2728*') or HasFootprint('3518*')] p9: gap=0.508 collisioncheckmode=3 verticalgap=0.508 showdistances=FALSE
ComponentClearance ComponentClearance_THtoSMT [IsThruComponent vs IsSMTComponent] p10: gap=0.254 collisioncheckmode=3 verticalgap=0.254 showdistances=FALSE
ComponentClearance ComponentClearance_THtoTH [IsThruComponent vs IsThruComponent] p11: gap=0.254 collisioncheckmode=3 verticalgap=0.254 showdistances=FALSE
DiffPairsRouting [All] p1: maxlimit=2.54 minlimit=0.254 mostfreqgap=0.254 toplayer_minwidth=0.381 toplayer_maxwidth=0.381 toplayer_prefwidth=0.381 midlayer1_minwidth=0.381 midlayer1_maxwidth=0.381 midlayer1_prefwidth=0.381 midlayer2_minwidth=0.381 midlayer2_maxwidth=0.381 midlayer2_prefwidth=0.381 midlayer3_minwidth=0.381 midlayer3_maxwidth=0.381 midlayer3_prefwidth=0.381 midlayer4_minwidth=0.381 midlayer4_maxwidth=0.381 midlayer4_prefwidth=0.381 midlayer5_minwidth=0.381 midlayer5_maxwidth=0.381 midlayer5_prefwidth=0.381 midlayer6_minwidth=0.381 midlayer6_maxwidth=0.381 midlayer6_prefwidth=0.381 midlayer7_minwidth=0.381 midlayer7_maxwidth=0.381 midlayer7_prefwidth=0.381 midlayer8_minwidth=0.381 midlayer8_maxwidth=0.381 midlayer8_prefwidth=0.381 bottomlayer_minwidth=0.381 bottomlayer_maxwidth=0.381 bottomlayer_prefwidth=0.381 maxuncoupledlength=25.4
FabricationTestPointUsage TestPointUsage [All] p1: valid=2 allowmultiple=FALSE
FabricationTestpoint Testpoint [All] p1: side=3 testpointundercomponent=TRUE minsize=1.016 maxsize=2.54 preferedsize=1.524 minholesize=0 maxholesize=1.016 preferedholesize=0.813 testpointgrid=0.025 allowsidetop=TRUE allowsidebottom=TRUE usegrid=TRUE gridtolerance=0
FanoutControl Fanout_LCC [IsLCC] p1: bgadir=Out bgaviamode=Centered fanoutstyle=Auto fanoutdirection=Alternating viagrid=0.025 // Fanout_LCC (Default Rule)
FanoutControl Fanout_BGA [IsBGA] p2: bgadir=Out bgaviamode=Centered fanoutstyle=Auto fanoutdirection=Alternating viagrid=0.025 // Fanout_BGA (Default Rule)
FanoutControl Fanout_Default [All] p4: bgadir=Out bgaviamode=Centered fanoutstyle=Auto fanoutdirection=Alternating viagrid=0.025 // Fanout_Default (Default Rule)
FanoutControl Fanout_Small [(CompPinCount < 5)] p5: bgadir=Out bgaviamode=Centered fanoutstyle=Auto fanoutdirection=OutThenIn viagrid=0.025 // Fanout_Small (Default Rule)
Height [All] p1: minheight=0 maxheight=76.2 prefheight=12.7
HoleSize [All] p1: absolutevalues=TRUE maxlimit=6.375 minlimit=0.2 maxpercent=80.000 minpercent=20.000
MinimumAnnularRing MinimumAnnularRing_ThermalPadVias [IsVia and InAnyComponent] p1: minimumring=0.15
MinimumAnnularRing [All] p2: minimumring=0.203
MinimumSolderMaskSliver MinimumSolderMaskSliver_Logo [InComponentClass('Logo') vs InComponentClass('Logo')] p1: minsoldermaskwidth=0.018
MinimumSolderMaskSliver [All] p2: minsoldermaskwidth=0.1
PlaneConnect [All] p1: planeconnectstyle=Direct reliefexpansion=0.254 reliefentries=4 reliefconductorwidth=0.254 reliefairgap=0.254
PolygonConnect PolygonConnect_15 [All vs IsNamedPolygon('C109_2') Or  IsNamedPolygon('C107_2') Or  IsNamedPolygon('HV') Or  IsNamedPolygon('Q203_5') Or  IsNamedPolygon('C107_2') Or  IsNamedPolygon('HS') Or  IsNamedPolygon('Q201_5') Or  IsNamedPolygon('Q203_5') Or  IsNamedPolygon('C106_2') Or  IsNamedPolygon('C108_2') Or  IsNamedPolygon('Vout') Or  IsNamedPolygon('Q203_5') Or  IsNamedPolygon('C108_2') Or  IsNamedPolygon('C113_2') Or  IsNamedPolygon('Q203_5') Or  IsNamedPolygon('Q201_5') Or  IsNamedPolygon('C107_2') Or  IsNamedPolygon('C102_1') Or  IsNamedPolygon('SGND') Or  IsNamedPolygon('GND') Or  IsNamedPolygon('SGND') Or  IsNamedPolygon('GND') Or  IsNamedPolygon('IN+') Or  IsNamedPolygon('IN+') Or  IsNamedPolygon('Q201_5') Or  IsNamedPolygon('Q201_5') Or  IsNamedPolygon('SGND') Or  IsNamedPolygon('SGND') Or  IsNamedPolygon('Vout') Or  IsNamedPolygon('Vout') Or  IsNamedPolygon('IN+') Or  IsNamedPolygon('GND') Or  IsNamedPolygon('IN+') Or  IsNamedPolygon('GND')] p1: connectstyle=Direct reliefconductorwidth=0.254 reliefentries=4 polygonreliefangle="90 Angle" airgapwidth=0.254
PolygonConnect PolygonConnect_14 [All vs IsNamedPolygon('C106_2') Or  IsNamedPolygon('C107_2') Or  IsNamedPolygon('C107_2') Or  IsNamedPolygon('C107_2') Or  IsNamedPolygon('C102_1') Or  IsNamedPolygon('Q203_5') Or  IsNamedPolygon('Vout') Or  IsNamedPolygon('Q203_5') Or  IsNamedPolygon('Q203_5') Or  IsNamedPolygon('Q201_5') Or  IsNamedPolygon('C108_2') Or  IsNamedPolygon('Q203_5') Or  IsNamedPolygon('HS') Or  IsNamedPolygon('HV') Or  IsNamedPolygon('C108_2') Or  IsNamedPolygon('Q201_5') Or  IsNamedPolygon('C109_2') Or  IsNamedPolygon('Q201_5') Or  IsNamedPolygon('Q201_5') Or  IsNamedPolygon('C113_2')] p2: connectstyle=Direct reliefconductorwidth=0.254 reliefentries=4 polygonreliefangle="90 Angle" airgapwidth=0.254
PolygonConnect PolygonConnect_13 [All vs IsNamedPolygon('C102_1') Or  IsNamedPolygon('HV') Or  IsNamedPolygon('C107_2') Or  IsNamedPolygon('C109_2') Or  IsNamedPolygon('C107_2') Or  IsNamedPolygon('C108_2') Or  IsNamedPolygon('C106_2') Or  IsNamedPolygon('C108_2') Or  IsNamedPolygon('C113_2') Or  IsNamedPolygon('C107_2')] p3: connectstyle=Direct reliefconductorwidth=0.254 reliefentries=4 polygonreliefangle="90 Angle" airgapwidth=0.254
PolygonConnect PolygonConnect_12 [All vs IsNamedPolygon('C107_2') Or  IsNamedPolygon('C113_2') Or  IsNamedPolygon('C106_2') Or  IsNamedPolygon('C107_2') Or  IsNamedPolygon('C107_2') Or  IsNamedPolygon('C102_1')] p4: connectstyle=Direct reliefconductorwidth=0.254 reliefentries=4 polygonreliefangle="90 Angle" airgapwidth=0.254
PolygonConnect PolygonConnect_11 [All vs IsNamedPolygon('C106_2') Or  IsNamedPolygon('C102_1') Or  IsNamedPolygon('C107_2') Or  IsNamedPolygon('C107_2') Or  IsNamedPolygon('C107_2')] p5: connectstyle=Direct reliefconductorwidth=0.254 reliefentries=4 polygonreliefangle="90 Angle" airgapwidth=0.254
PolygonConnect PolygonConnect_10 [All vs IsNamedPolygon('C106_2')] p6: connectstyle=Direct reliefconductorwidth=0.254 reliefentries=4 polygonreliefangle="90 Angle" airgapwidth=0.254
PolygonConnect PolygonConnect_9 [All vs IsNamedPolygon('C11_1') Or  IsNamedPolygon('Vin') Or  IsNamedPolygon('Vin') Or  IsNamedPolygon('5V') Or  IsNamedPolygon('D6_2') Or  IsNamedPolygon('Q3_3') Or  IsNamedPolygon('GND2') Or  IsNamedPolygon('GND2') Or  IsNamedPolygon('GND') Or  IsNamedPolygon('Q3_4') Or  IsNamedPolygon('12V5') Or  IsNamedPolygon('GND') Or  IsNamedPolygon('12V5') Or  IsNamedPolygon('D3_1')] p7: connectstyle=Direct reliefconductorwidth=0.254 reliefentries=4 polygonreliefangle="90 Angle" airgapwidth=0.254
PolygonConnect PolygonConnect_8 [All vs IsNamedPolygon('C11_1') Or  IsNamedPolygon('Vin') Or  IsNamedPolygon('12V5') Or  IsNamedPolygon('Q3_3') Or  IsNamedPolygon('GND2') Or  IsNamedPolygon('GND2') Or  IsNamedPolygon('5V') Or  IsNamedPolygon('Q3_4') Or  IsNamedPolygon('12V5')] p8: connectstyle=Direct reliefconductorwidth=0.254 reliefentries=4 polygonreliefangle="90 Angle" airgapwidth=0.254
PolygonConnect PolygonConnect_7 [All vs IsNamedPolygon('GND2') Or  IsNamedPolygon('GND2') Or  IsNamedPolygon('5V') Or  IsNamedPolygon('12V5') Or  IsNamedPolygon('12V5') Or  IsNamedPolygon('C11_1')] p9: connectstyle=Direct reliefconductorwidth=0.254 reliefentries=4 polygonreliefangle="90 Angle" airgapwidth=0.254
PolygonConnect PolygonConnect_6 [All vs IsNamedPolygon('GND2') Or  IsNamedPolygon('SGND') Or  IsNamedPolygon('GND1') Or  IsNamedPolygon('C901_1') Or  IsNamedPolygon('SGND') Or  IsNamedPolygon('GND2') Or  IsNamedPolygon('GND1')] p10: connectstyle=Direct reliefconductorwidth=0.254 reliefentries=4 polygonreliefangle="90 Angle" airgapwidth=0.254
PolygonConnect PolygonConnect_5 [All vs IsNamedPolygon('GND1') Or  IsNamedPolygon('GND1')] p11: connectstyle=Direct reliefconductorwidth=0.254 reliefentries=4 polygonreliefangle="90 Angle" airgapwidth=0.254
PolygonConnect PolygonConnect_4 [All vs IsNamedPolygon('C21_1') Or  IsNamedPolygon('C5_1') Or  IsNamedPolygon('C12_2') Or  IsNamedPolygon('C2_2') Or  IsNamedPolygon('C13_1') Or  IsNamedPolygon('C28_1') Or  IsNamedPolygon('C6_1') Or  IsNamedPolygon('GND') Or  IsNamedPolygon('GND2') Or  IsNamedPolygon('C14_1') Or  IsNamedPolygon('C13_1') Or  IsNamedPolygon('Q1_3') Or  IsNamedPolygon('C14_1') Or  IsNamedPolygon('C5_1') Or  IsNamedPolygon('GND2') Or  IsNamedPolygon('C28_1') Or  IsNamedPolygon('D5_2') Or  IsNamedPolygon('D6_2') Or  IsNamedPolygon('D2_1') Or  IsNamedPolygon('C12_2') Or  IsNamedPolygon('D2_1') Or  IsNamedPolygon('C4_1') Or  IsNamedPolygon('C4_1') Or  IsNamedPolygon('C2_2') Or  IsNamedPolygon('GND') Or  IsNamedPolygon('C33_1') Or  IsNamedPolygon('C9_1')] p12: connectstyle=Direct reliefconductorwidth=0.254 reliefentries=4 polygonreliefangle="90 Angle" airgapwidth=0.254
PolygonConnect PolygonConnect_3 [All vs IsNamedPolygon('C28_1') Or  IsNamedPolygon('C12_2') Or  IsNamedPolygon('C28_1') Or  IsNamedPolygon('C9_1') Or  IsNamedPolygon('D5_2') Or  IsNamedPolygon('C12_2') Or  IsNamedPolygon('C2_2') Or  IsNamedPolygon('C14_1') Or  IsNamedPolygon('C4_1') Or  IsNamedPolygon('C14_1') Or  IsNamedPolygon('D6_2') Or  IsNamedPolygon('GND2') Or  IsNamedPolygon('Q1_3') Or  IsNamedPolygon('C5_1') Or  IsNamedPolygon('D2_1') Or  IsNamedPolygon('C4_1') Or  IsNamedPolygon('C13_1') Or  IsNamedPolygon('C5_1') Or  IsNamedPolygon('C13_1') Or  IsNamedPolygon('C33_1') Or  IsNamedPolygon('D2_1') Or  IsNamedPolygon('GND') Or  IsNamedPolygon('GND') Or  IsNamedPolygon('GND2') Or  IsNamedPolygon('C2_2') Or  IsNamedPolygon('C6_1') Or  IsNamedPolygon('C21_1')] p13: connectstyle=Direct reliefconductorwidth=0.254 reliefentries=4 polygonreliefangle="90 Angle" airgapwidth=0.254
PolygonConnect PolygonConnect_2 [All vs IsNamedPolygon('C21_1') Or  IsNamedPolygon('C4_1') Or  IsNamedPolygon('D5_2') Or  IsNamedPolygon('C5_1') Or  IsNamedPolygon('C14_1') Or  IsNamedPolygon('C13_1') Or  IsNamedPolygon('C4_1') Or  IsNamedPolygon('C33_1') Or  IsNamedPolygon('C12_2') Or  IsNamedPolygon('D2_1') Or  IsNamedPolygon('C2_2') Or  IsNamedPolygon('C28_1') Or  IsNamedPolygon('C12_2') Or  IsNamedPolygon('D2_1') Or  IsNamedPolygon('C5_1') Or  IsNamedPolygon('Q1_3') Or  IsNamedPolygon('GND') Or  IsNamedPolygon('D6_2') Or  IsNamedPolygon('C6_1') Or  IsNamedPolygon('C2_2') Or  IsNamedPolygon('C14_1') Or  IsNamedPolygon('C28_1') Or  IsNamedPolygon('C13_1') Or  IsNamedPolygon('C9_1') Or  IsNamedPolygon('GND')] p14: connectstyle=Direct reliefconductorwidth=0.254 reliefentries=4 polygonreliefangle="90 Angle" airgapwidth=0.254
PolygonConnect PolygonConnect_1 [All vs IsNamedPolygon('C28_1') Or  IsNamedPolygon('D5_2') Or  IsNamedPolygon('C5_1') Or  IsNamedPolygon('C5_1') Or  IsNamedPolygon('D2_1') Or  IsNamedPolygon('C21_1') Or  IsNamedPolygon('C9_1') Or  IsNamedPolygon('C4_1') Or  IsNamedPolygon('C14_1') Or  IsNamedPolygon('C28_1') Or  IsNamedPolygon('C6_1') Or  IsNamedPolygon('C12_2') Or  IsNamedPolygon('C33_1') Or  IsNamedPolygon('C4_1') Or  IsNamedPolygon('C13_1') Or  IsNamedPolygon('C12_2') Or  IsNamedPolygon('D6_2') Or  IsNamedPolygon('C2_2') Or  IsNamedPolygon('C14_1') Or  IsNamedPolygon('D2_1') Or  IsNamedPolygon('C2_2') Or  IsNamedPolygon('C13_1')] p15: connectstyle=Direct reliefconductorwidth=0.254 reliefentries=4 polygonreliefangle="90 Angle" airgapwidth=0.254
PolygonConnect [All] p16: connectstyle=Direct reliefconductorwidth=0.254 reliefentries=4 polygonreliefangle="90 Angle" airgapwidth=0.254
RoutingVias ThermalPadVias [IsVia and InAnyComponent] p1: holewidth=0.2 width=0.5 viastyle="Through Hole" minholewidth=0.2 minwidth=0.5 maxholewidth=0.33 maxwidth=0.6
RoutingVias [All] p2: holewidth=0.406 width=0.864 viastyle="Through Hole" minholewidth=0.2 minwidth=0.508 maxholewidth=1.016 maxwidth=1.651
SilkToBoardRegionClearance [Not ((IsComment or IsDesignator) And (Hide <> 'False')) and not InRegion(1000,500,4000,800)] p1:
SilkToSilkClearance SilkToSilkClearance_Pb-FreeLogo [(HasFootprint('Pb-Free_Overlay_Medium') OR HasFootprint('Pb-Free_Overlay_Small')) vs (HasFootprint('Pb-Free_Overlay_Medium') OR HasFootprint('Pb-Free_Overlay_Small'))] p1: silktosilkclearance=0
SilkToSilkClearance [All] p2: silktosilkclearance=0.051
SilkToSolderMaskClearance [IsVia] p1: minsilkscreentomaskgap=0 clearancetoexposedcopper=TRUE
SilkToSolderMaskClearance SilkToComponentPadClearance [IsPad and InAnycomponent] p2: minsilkscreentomaskgap=0.102 clearancetoexposedcopper=TRUE
SilkToSolderMaskClearance "Silk to Solder Mask Opening" [All] p3: minsilkscreentomaskgap=0.076 clearancetoexposedcopper=FALSE
SolderMaskExpansion [All] p1: expansion=0.05 istentingtop=FALSE
Width [All] p1: maxlimit=2.54 minlimit=0.152 preferedwidth=0.254 checkconnectedcopper=TRUE
14 further rules are at their usual default settings.

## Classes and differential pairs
component class Connector: J1 J2 J4 Logo1 Logo2 Logo3 MP1 MP2 MP3 MP4
component class Telemetry: C3 C4 C5 C14 C16 C26 C28 C30 C31 C60 C61 C88 C89 C90 C91 C92 C93 C94 C95 C96 C97 C98 C99 C100 C126 C127 C128 C129 LDO_BODE "MSP430 JTAG" "MSP430 Tool/Target" Q3 R4 R5 R6 R7 R8 R9 R10 R11 R12 R13 R14 R15 R16 R17 R18 R19 R20 R21 R22 R23 R24 R25 R26 R27 R28 R29 R30 R31 R71 R73 R79 R80 R81 R82 R83 R84 U1 U2 U3 U8 U9 UART/D UART/R Y1
component class "12V to 5V": 5V "5V Bode" 5V_EN C15 C58 C59 C62 C63 C64 C65 C66 C67 C68 C70 C73 C74 C75 C76 C77 D2 L2 LDOCAP R32 R36 R39 R41 R43 R67 R68 R69 R70 R72 R74 R75 SGND U7
component class "12V Bias": !PCB401 C1 C2 C6 C7 C8 C9 C10 C11 C12 C13 C37 C38 C39 C40 C41 C42 C43 C44 C45 C46 C47 C48 C49 C50 C51 C52 C53 C54 C55 C56 C57 D5 D6 D7 D8 L3 Q1 Q2 R46 R47 R48 R49 R50 R51 R52 R53 R54 R55 R56 R57 R58 R59 R60 R61 R62 R63 R64 R65 R66 R77 R78 T1 T2 U5 U6
component class "12 to 3.3V": "3.3V Bode" "3.3V Comp" 3.3V_EN 3.3V_Out C17 C18 C21 C22 C23 C24 C25 C27 C29 C32 C33 C34 C35 C36 D1 L1 R3 R33 R34 R35 R37 R38 R40 R42 R44 R45 SGND_3 U4
component class "28V to 12V drivers": !PCB201 C201 C202 C203 C204 C205 C206 C207 C208 C209 C210 C211 C212 C213 C214 C305 C306 D201 D202 D203 D204 R201 R202 R203 R204 R205 R206 R207 R208 R209 R210 R211 R212 R213 R214 R215 R216 R217 R218 R219 R220 R221 R222 R223 R224 R225 R226 R227 R228 R229 R230 R231 R232 R233 R234 R235 R236 R237 R238 U201 U202 U203
component class Header: 3.3V_EN 5V_EN 12V_EN "Full Bridge Bode" "MSP430 Tool/Target" UART/D UART/R

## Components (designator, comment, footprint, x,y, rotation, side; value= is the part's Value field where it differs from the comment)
"3.3V Bode" "BODE_INJ" Keystone5012 -6.465,-10.516 r0 top
"3.3V Comp" "VCOMP" Keystone5012 -6.465,-6.633 r0 top
3.3V_EN "PTT-103-01-L-S" Samtec_PTT-103-01-x-S -29.107,-9.103 r270 top
3.3V_Out "3.3V_OUT" Keystone5010 -24.188,-33.77 r0 top
5V "5V" Keystone5010 -5.885,-36.77 r90 top
"5V Bode" "BODE_INJ" Keystone5012 -34.384,-38.42 r0 top
5V_EN "PTT-103-01-L-S" Samtec_PTT-103-01-x-S -32.901,-63.403 r180 top
12V "5010" Keystone5010 -33.702,-8.75 r270 top
12V_EN "PTT-103-01-L-S" Samtec_PTT-103-01-x-S -143.426,-17.752 r90 top
12Vp_EXT "5010" Keystone5010 -74.846,-71.568 r270 top
12Vs_EXT "5010" Keystone5010 -48.684,-36.516 r90 top
C1 "GRM32ER72A105KA01L" 1210_270 -43.609,-74.1 r270 top value=1uF
C2 "GRM32ER72A105KA01L" 1210_270 -40.175,-74.1 r270 top value=1uF
C3 "CL10B104KO8WPNC" 0603 -76.544,-30.923 r270 top value=0.1uF
C4 "C0603C105K3RACTU" 0603 -74.93,-30.899 r270 top value=1uF
C5 "C0603X222K5RACTU" 0603 -88.778,-30.513 r270 top value=2200pF
C6 "GRM32ER72A105KA01L" 1210_270 -6.774,-78.119 r270 top value=1uF
C7 "GRM32ER72A105KA01L" 1210_270 -50.449,-79.245 r270 top value=1uF
C8 "GRM32ER72A105KA01L" 1210_270 -46.996,-79.245 r270 top value=1uF
C9 "GRM32ER72A105KA01L" 1210_270 -53.902,-79.245 r270 top value=1uF
C10 "GRM32ER72A105KA01L" 1210_270 -43.543,-79.245 r270 top value=1uF
C11 "GRM32ER72A105KA01L" 1210_270 -60.808,-79.245 r270 top value=1uF
C12 "GRM32ER72A105KA01L" 1210_270 -57.355,-79.245 r270 top value=1uF
C13 "GRM32ER72A105KA01L" 1210_270 -40.091,-79.245 r270 top value=1uF
C14 "C0402C100K4GACTU" 0402 -72.849,-28.896 r180 top value=10pF
C15 "T530X337M010ATE006" 7343-43 -10.637,-47.126 r180 top value=330uF
C16 "C0402C100K4GACTU" 0402 -72.849,-25.594 r180 top value=10pF
C17 "T521D107M025ATE040" FP-T521D107M025ATE040_2917-MFG -29.767,-27.069 r180 top value=100µF
C18 "T521D107M025ATE040" FP-T521D107M025ATE040_2917-MFG -29.767,-22.047 r180 top value=100µF
C19 "GCM32EL8EH106KA07L" 1210_270 -95.844,-79.245 r270 top value=10uF
C20 "GCM32EL8EH106KA07L" 1210_270 -99.379,-79.245 r270 top value=10uF
C21 "GRM21BR61E226ME44L" 0805_HV -32.721,-16.938 r270 top value=22uF
C22 "GRM21BZ71E106KE15L" 0805_HV -30.323,-16.938 r270 top value=10uF
C23 "CL21B105KBFNFNE" 0805 -27.974,-16.775 r270 top value=1uF
C24 "C0805C104K5RACAUTO" 0805_HV -25.529,-16.938 r270 top value=0.1uF
C25 "T530X337M010ATE006" 7343-43 -19.633,-29.611 r180 top value=330uF
C26 "GCM188R71E104KA57D" 0603 -42.461,-30.255 r270 top value=0.1uF
C27 "CL32B226KOJVPNE" 1210_270 -13.214,-29.448 r90 top value=22uF
C28 "GCM188R71E104KA57D" 0603 -43.985,-30.255 r90 top value=0.1uF
C29 "CL21B105KBFNFNE" 0805 -10.401,-28.851 r90 top value=1uF
C30 "GCM188R71E104KA57D" 0603 -46.779,-21.822 r90 top value=0.1uF
C31 "GCM188R71E104KA57D" 0603 -45.266,-21.836 r90 top value=0.1uF
C32 "C1608X7R1H474K080AC" 0603 -16.504,-6.506 r0 top value=0.47uF
C33 "885012206091" FP-885012206091_0603-MFG -12.87,-9.846 r180 bottom value=22nF
C34 "CL21B105KBFNFNE" 0805L -25.697,-11.352 r180 top value=1uF
C35 "06035A470JAT2A" 0603 -12.538,-6.75 r0 top value=47pF
C36 "885012206089" 0603 -16.504,-5.045 r180 top value=0.01uF
C37 "C0603C105K3RACTU" 0603 -66.88,-67.507 r180 top value=1uF
C38 "GRM21BR61H475KE51L" 0805_HV1 -67.642,-58.415 r90 top value=4.7uF
C39 "GRM21BR61H475KE51L" 0805_HV1 -49.799,-47.36 r0 top value=4.7uF
C40 "GRM21BR61H475KE51L" 0805_HV1 -49.799,-49.9 r0 top value=4.7uF
C41 "GRM21BR61H475KE51L" 0805_HV1 -49.799,-52.44 r0 top value=4.7uF
C42 "C0603C105K3RACTU" 0603 -59.006,-58.998 r180 top value=1uF
C43 "C0603C105K3RACTU" 0603 -60.022,-70 r270 top value=1uF
C44 "C0603C105K3RACTU" 0603 -70.528,-37.608 r90 top value=1uF
C45 "GRM21BZ71E106KE15L" 0805_HV1 -72.687,-37.532 r270 top value=10uF
C46 "GRM21BZ71E106KE15L" 0805_HV1 -72.433,-40.199 r0 top value=10uF
C47 "GRM1885C2A471JA01D" 0603_HV -56.974,-54.553 r270 top value=470pF
C48 "GRM1885C1H220JA01D" 0603_HV -51.249,-60.216 r270 top value=22pF
C49 "C0603C105K3RACTU" 0603 -70.592,-49.765 r90 top value=1uF
C50 "GRM21BZ71E106KE15L" 0805_HV1 -73.773,-52.328 r0 top value=10uF
C51 "GRM21BZ71E106KE15L" 0805_HV1 -73.773,-54.36 r0 top value=10uF
C52 "GRM188R71E103KA01D" 0603_HV -62.281,-59.328 r90 top value=0.01uF
C53 "GRM188R71E102KA01D" 0603_HV -54.585,-70 r90 top value=1000pF
C54 "GCM188R71C474KA55D" 0603_HV -55.941,-70 r270 top value=0.47uF
C55 "GRM188R71E154KA01D" 0603_HV -49.725,-63.264 r90 top value=0.15uF
C56 "GRM188R71H821KA01D" 0603_HV -51.249,-63.264 r90 top value=820pF
C57 "GRM188R71E102KA01D" 0603_HV -53.207,-70 r90 top value=1000pF
C58 "T521D107M025ATE040" FP-T521D107M025ATE040_2917-MFG -17.438,-60.393 r270 top value=100µF
C59 "T521D107M025ATE040" FP-T521D107M025ATE040_2917-MFG -22.524,-60.393 r270 top value=100µF
C60 "GCM188R71E104KA57D" 0603 -88.689,-33.887 r90 top value=0.1uF
C61 "0603ZC101KAT2A" 0603 -81.361,-36.135 r180 top value=100pF
C62 "GRM21BR61E226ME44L" 0805_HV -26.926,-64.714 r0 top value=22uF
C63 "GRM21BZ71E106KE15L" 0805_HV -26.926,-57.278 r0 top value=10uF
C64 "CL21B105KBFNFNE" 0805 -27.088,-59.709 r0 top value=1uF
C65 "C0805C104K5RACAUTO" 0805_HV -26.926,-62.236 r0 top value=0.1uF
C66 "T530X337M010ATE006" 7343-43 -10.637,-56.981 r180 top value=330uF
C67 "T530X337M010ATE006" 7343-43 -10.637,-52.042 r180 top value=330uF
C68 "CL32B226KOJVPNE" 1210_270 -12.161,-43.072 r180 top value=22uF
C70 "CL21B105KBFNFNE" 0805 -12.761,-40.352 r180 top value=1uF
C73 "C1608X7R1H474K080AC" 0603 -36.367,-47.952 r270 top value=0.47uF
C74 "885012206091" FP-885012206091_0603-MFG -32.57,-43.79 r270 bottom value=22nF
C75 "CL21B105KBFNFNE" 0805L -33.64,-58.133 r270 top value=1uF
C76 "06035A470JAT2A" 0603 -36.311,-43.79 r90 top value=47pF
C77 "885012206089" 0603 -33.295,-43.79 r90 top value=0.01uF
C88 "CL10B104KO8WPNC" 0603 -76.63,-24.182 r90 top value=0.1uF
C89 "C0603C105K3RACTU" 0603 -74.989,-24.173 r90 top value=1uF
C90 "CL10B101KB8NNNC" 0603L -44.62,-33.849 r270 top value=100pF
C91 "CL10B101KB8NNNC" 0603L -40.81,-31.563 r270 top value=100pF
C92 "CL10B101KB8NNNC" 0603L -46.674,-30.226 r180 top value=100pF
C93 "CL10B101KB8NNNC" 0603L -40.81,-29.023 r270 top value=100pF
C94 "CL10B101KB8NNNC" 0603L -43.688,-21.779 r90 top value=100pF
C95 "CL10B101KB8NNNC" 0603L -42.436,-21.827 r90 top value=100pF
C96 "GRM188R61E106KA73D" 0603 -64.721,-23.108 r270 bottom value=10uF
C97 "C0603C105K3RACTU" 0603 -63.027,-23.108 r270 bottom value=1uF
C98 "GCM188R71E104KA57D" 0603 -61.415,-23.108 r270 bottom value=0.1uF
C99 "T510X476M035ATE055" FP-T510X476M035ATE055_2917-MFG -50.805,-23.213 r90 top value=47µF
C100 "C0603C105K3RACTU" 0603 -50.17,-23.022 r270 bottom value=1uF
C101 "GRM188R71E105KA12D" 0603_HV -128.704,-30.36 r270 top value=1uF
C102 "T494X226K050AT" 7343-43 -104.271,-77.3 r270 top value=22uF
C103 "T494X226K050AT" 7343-43 -109.544,-77.3 r270 top value=22uF
C104 "GRM188Z71C225KE43" 0603_HV -136.44,-28.853 r0 top value=2.2uF
C105 "GRM188R71E562KA01D" 0603_HV -127.967,-35.613 r180 top value=5600pF
C106 "GCM188R71E104KA57D" 0603_HV -140.758,-38.251 r180 top value=0.1uF
C107 "GCM32EL8EH106KA07L" 1210_270 -88.837,-79.245 r270 top value=10uF
C108 "GCM32EL8EH106KA07L" 1210_270 -92.393,-79.245 r270 top value=10uF
C109 "GCM188R71C474KA55D" 0603_HV -140.758,-35.203 r0 top value=0.47uF
C110 "GCM1885C2A100JA16D" 0603_HV -140.758,-32.155 r180 top value=10pF
C111 "GRM188R71E682KA01D" 0603L -132.588,-39.624 r270 top value=6800pF
C112 "GRM1885C1H121JA01D" 0603_HV -135.551,-39.648 r270 top value=120pF
C113 "GRM1885C1H101JA01D" 0603_HV -142.866,-21.658 r0 top value=100pF
C114 "GRM1885C1H101JA01D" 0603_HV -142.866,-22.913 r0 top value=100pF
C115 "GRM188R71E105KA12D" 0603_HV -46.996,-8.163 r90 bottom value=1uF
C116 "GRM188R71E105KA12D" 0603_HV -48.52,-8.163 r90 bottom value=1uF
C117 "GRM2165C2A122JA01D" 0805L -117.941,-33.612 r270 top value=1200pF
C118 "GRM2165C2A122JA01D" 0805_HV -119.085,-3.623 r0 top value=1200pF
C119 "GRM31CR71E106MA12L" 1206 -63.242,-7.083 r90 bottom value=10uF
C120 "GRM31CR71E106MA12L" 1206 -60.303,-7.083 r90 bottom value=10uF
C121 "TPSV107K025R0100" 7361-38 -51.67,-7.274 r90 top value=100uF
C122 "GRM319R72A104KA01D" 1206 -104.437,-5.087 r180 top value=0.1uF
C123 "TPSV107K025R0100" 7361-38 -44.685,-7.274 r90 top value=100uF
C124 "TPSV107K025R0100" 7361-38 -65.64,-7.274 r90 top value=100uF
C125 "TPSV107K025R0100" 7361-38 -58.655,-7.274 r90 top value=100uF
C126 "GCM188R71E104KA57D" 0603 -51.872,-23.022 r270 bottom value=0.1uF
C127 "06031C102JAT2A" 0603 -64.739,-25.735 r270 top value=1000pF
C128 "C0603C472J5RAC7867" FP-C0603C472J5RAC7867_0603-MFG -59.86,-28.769 r90 top value=4.7nF
C129 "UMK107B7474KA-TR" 0603 -53.871,-25.518 r270 top value=0.47uF
C201 "C0603C105K3RACTU" 0603 -132.78,-51.383 r90 top value=1uF
C202 "C0603C105K3RACTU" 0603 -131.393,-51.383 r270 top value=1uF
C203 "C0603C104K5RACAUTO" 0603_HV -131.366,-48.011 r270 top value=0.1uF
C204 "C0603C105K3RACTU" 0603 -120.075,-50.121 r270 top value=1uF
C205 "GRM188Z71C225KE43" 0603_HV -120.064,-57.621 r90 top value=2.2uF
C206 "C0603C105K3RACTU" 0603 -79.16,-66.338 r270 top value=1uF
C207 "C0603C105K3RACTU" 0603 -80.76,-66.338 r90 top value=1uF
C208 "C0603C104K5RACAUTO" 0603_HV -80.775,-69.698 r90 top value=0.1uF
C209 "C0603C105K3RACTU" 0603 -91.985,-68.158 r90 top value=1uF
C210 "GRM188Z71C225KE43" 0603_HV -91.985,-60.658 r270 top value=2.2uF
C211 "C0603C105K3RACTU" 0603 -140.478,-15.032 r180 top value=1uF
C212 "C0603C105K3RACTU" 0603 -140.543,-13.402 r0 top value=1uF
C213 "GRM188Z71C225KE43" 0603_HV -127.683,-14.054 r90 top value=2.2uF
C214 "GRM188Z71C225KE43" 0603_HV -127.683,-21.554 r90 top value=2.2uF
C301 "GRM21BR71E475KA73L" 0805_HV -57.664,-7.604 r90 bottom value=4.7uF
C302 "GRM21BR71E475KA73L" 0805_HV -55.378,-7.604 r90 bottom value=4.7uF
C303 "GRM21BR71E475KA73L" 0805_HV -53.092,-7.604 r90 bottom value=4.7uF
C304 "GRM21BR71E475KA73L" 0805_HV -50.703,-7.604 r90 bottom value=4.7uF
C305 "GRM1885C1H101JA01D" 0603_HV -132.162,-59.637 r0 top value=100pF
C306 "GRM1885C1H101JA01D" 0603_HV -79.548,-59.951 r180 top value=100pF
D1 "SS10P4-M3/86A" FP-SS10P4-M3_86A_SMPC-MFG -19.942,-24.663 r270 top
D2 "SS10P4-M3/86A" FP-SS10P4-M3_86A_SMPC-MFG -18.017,-50.201 r0 top
D3 "MBRS1100T3G" SMB -118.564,-48.762 r270 bottom value=100V
D4 "MBRS1100T3G" SMB -93.96,-69.033 r90 bottom value=100V
D5 "1N6263W-7-F" SOD-123 -64.848,-60.141 r90 top value=60V
D6 "SS16T3G" SMA -68.179,-36.684 r90 top value=60V
D7 "SS16T3G" SMA -68.179,-53.678 r0 top value=60V
D8 "1N6263W-7-F" SOD-123 -63.451,-54.934 r90 top value=60V
D9 "MBRS1100T3G" SMB -118.564,-56.736 r270 bottom value=100V
D10 "MBRS1100T3G" SMB -93.96,-61.208 r90 bottom value=100V
D101 "BAT46GWJ" FP-BAT46GWJ_SOD-123-MFG -142.55,-76.19 r270 top
D102 "BAT46GWJ" FP-BAT46GWJ_SOD-123-MFG -142.662,-68.606 r90 top
D103 "BAT46GWJ" FP-BAT46GWJ_SOD-123-MFG -140.482,-76.19 r90 top
D104 "BAT46GWJ" FP-BAT46GWJ_SOD-123-MFG -140.407,-68.606 r270 top
D105 "PMEG4030ER,115" SOD-123W -135.12,-26.913 r180 top value=40V
D106 "MBRS1100T3G" SMB -120.891,-29.064 r180 top value=100V
D107 "MBRS1100T3G" SMB -120.871,-6.925 r180 top value=100V
D108 "PMEG4030ER,115" SOD-123W -139.945,-27.17 r270 top value=40V
D109 "MBRS1100T3G" SMB -99.484,-7.56 r270 top value=100V
D110 "MBRS1100T3G" SMB -105.885,-8.703 r180 top value=100V
D111 "PMEG4030ER,115" SOD-123W -140.632,-59.119 r90 top value=40V
D112 "PMEG4030ER,115" SOD-123W -83.609,-40.834 r270 top value=40V
D113 "1N4148W-TP" SOD-123 -136.314,-47.184 r90 top value=100V
D114 "1N4148W-TP" SOD-123 -79.275,-49.668 r0 top value=100V
D201 "SS1H20LW" FP-SS1H20LW_SOD-123W-MFG -132.703,-45.209 r180 top
D202 "MMSZ5243B-7-F" SOD-123 -126.689,-43.714 r0 top value=13V
D203 "SS1H20LW" FP-SS1H20LW_SOD-123W-MFG -79.07,-72.255 r0 top
D204 "MMSZ5243B-7-F" SOD-123 -84.484,-74.362 r180 top value=13V
"Full Bridge Bode" "PTT-103-01-L-S" Samtec_PTT-103-01-x-S -142.918,-45.279 r270 top
J1 "6450839-7" FP-6450839-7_CONN_PWR_HDR_8-32-MFG 8.72,-42.37 r90 top
J2 "1-2000713-2" FP-1-2000713-2_HDR1-MFG 9.622,-0.007 r90 top
J4 "1-2000713-2" FP-1-2000713-2_HDR1-MFG 9.622,-84.71 r90 top
L1 "XGL1060-472MEC" FP-XGL1060-472MEC_SMT_IND_10MM0_11MM3-MFG -9.502,-19.823 r0 top value=4.7uH
L2 "XGL1060-182MEC" FP-XGL1060-182MEC_SMT2_10MM0_11MM3-MFG -21.238,-40.996 r90 top value=1.8uH
L3 "XGL1010-103MED" FP-XGL1010-103MED_SMT_IND_10MM0_11MM3-MFG -28.552,-77.216 r180 top value=10uH
L101 "7443556130" WE-HCB_1890 -78.806,-12.8 r0 top value=1.3uH
L102 "LPD4012-223MRB" LPD4012 -138.727,-54.194 r0 top value=22uH
L103 "LPD4012-223MRB" LPD4012 -80.012,-45.526 r270 top value=22uH
L301 "1212VS-111MED" FP-1212VS-111MED_SMT_IND_11MM5_12MM0-MFG -95.662,-47.744 r90 top value=117nH
LDO_BODE "LDO_BODE" Keystone5002 -57.529,-29.016 r0 top
LDOCAP "5V" Keystone5010 -30.53,-38.412 r90 top
Logo1 "WEEE logo" WEEE_Minimum -79.164,-86.427 r90 top
Logo2 "FCC disclaimer" FCC_disclaimer 63.33,-82.871 r90 top
Logo3 "CAUTION.  READ USER GUIDE BEFORE USE" IEC_Caution_Small -91.356,-86.554 r90 top
MP1 "2563" FP-2563_RUBBER_BUMPER-MFG -15.537,-81.982 r180 bottom
MP2 "2563" FP-2563_RUBBER_BUMPER-MFG -110.279,-81.982 r180 bottom
MP3 "2563" FP-2563_RUBBER_BUMPER-MFG -15.537,-2.226 r180 bottom
MP4 "2563" FP-2563_RUBBER_BUMPER-MFG -110.279,-2.226 r180 bottom
"MSP430 JTAG" "SBH11-PBPC-D07-ST-BK" CONN_SBH11-PBPC-D07-ST-BK -136.314,-3.877 r180 bottom
"MSP430 Tool/Target" "PTT-103-01-L-S" Samtec_PTT-103-01-x-S -143.426,-11.402 r270 top
PGND_1 "5011" Keystone5011 -65.353,-80.974 r0 top
Q1 "MMUN2214LT1G" SOT-23 -66.88,-64.713 r90 top value="50 V"
Q2 "EPC7003AC" FP-EPC7003AC_FSMD-A-MFG -53.799,-54.426 r90 top
Q3 "2N2222AUB" FP-2N2222AUB_SMT3-IPC_A -125.966,-6.791 r90 top value=50V
Q101 "EPC7018GC" FP-EPC7018GC_FSMD-G-MFG -113.556,-47.574 r90 top
Q102 "EPC7018GC" FP-EPC7018GC_FSMD-G-MFG -113.556,-57.846 r90 top
Q103 "EPC7018GC" FP-EPC7018GC_FSMD-G-MFG -98.265,-68.681 r270 top
Q104 "EPC7018GC" FP-EPC7018GC_FSMD-G-MFG -98.519,-58.369 r270 top
Q105 "EPC7018GC" FP-EPC7018GC_FSMD-G-MFG -121.245,-22.605 r90 top
Q106 "EPC7018GC" FP-EPC7018GC_FSMD-G-MFG -121.191,-13.256 r90 top
Q107 "BSS138" SOT-23 -142.979,-54.861 r270 top value=50V
Q108 "BSS138" SOT-23 -79.037,-40.637 r90 top value=50V
Q109 "MMBT2907A" SOT-23 -135.933,-58.995 r180 top value="60 V"
Q110 "MMBT2907A" SOT-23 -84.682,-50.806 r180 top value="60 V"
R1 "KRL2012E-M-R004-F-T5" FP-KRL2012E-M-R004-F-T5_2012-MFG -67.286,-16.85 r0 top value=4m
R2 "KRL2012E-M-R004-F-T5" FP-KRL2012E-M-R004-F-T5_2012-MFG -67.286,-13.648 r0 top value=4m
R3 "KRL2012E-M-R015-F-T5" FP-KRL2012E-M-R015-F-T5_0508-MFG -6.515,-27.005 r270 top value=15m
R4 "RC0603FR-0712KL" 0603 -46.868,-33.135 r180 top value=12.0k
R5 "RC0603FR-0712KL" 0603 -38.594,-29.316 r0 top value=12.0k
R6 "CRCW0603715KFKEA" 0603 -43.223,-33.684 r270 top value=715k
R7 "CRCW0603750KFKEA" 0603 -38.594,-30.921 r0 top value=750k
R8 "RC0603FR-0712KL" 0603 -46.871,-31.589 r180 top value=12.0k
R9 "RC0603FR-0712KL" 0603 -38.594,-27.755 r0 top value=12.0k
R10 "CRCW0603715KFKEA" 0603 -46.69,-28.896 r0 top value=715k
R11 "CRCW0603750KFKEA" 0603 -38.594,-26.185 r0 top value=750k
R12 "RC0603FR-0712KL" 0603 -44.218,-18.532 r90 top value=12.0k
R13 "CRCW0603806KFKEA" 0603 -45.856,-18.532 r90 top value=806k
R14 "RC0603FR-0712KL" 0603 -42.643,-18.532 r90 top value=12.0k
R15 "CRCW0603806KFKEA" 0603 -41.009,-18.532 r90 top value=806k
R16 "RC0603FR-071KL" 0603 -82.747,-37.541 r180 top value=1.00k
R17 "RC0603FR-071KL" 0603 -79.594,-37.543 r0 top value=1.00k
R18 "RC0603FR-075K1L" 0603 -86.194,-34.542 r0 top value=5.10k
R19 "RC0603FR-075K1L" 0603 -86.194,-33.128 r0 top value=5.10k
R20 "RC0603FR-075K1L" 0603 -76.598,-33.2 r180 top value=5.10k
R21 "RC0603FR-075K1L" 0603 -76.569,-34.644 r180 top value=5.10k
R22 "RC0603FR-0710KL" 0603 -53.871,-21.056 r270 top value=10.0k
R23 "ERJ-3EKF4992V" 0603 -63.215,-21.283 r90 top value=49.9k
R24 "RC0603FR-0747KL" 0603 -87.383,-30.494 r270 top value=47.0k
R25 "CRCW060310K0FKEA" 0603 -40.085,-23.739 r180 bottom value=10.0k
R26 "CRCW060310K0FKEA" 0603 -40.085,-22.079 r180 bottom value=10.0k
R27 "RC0603FR-0740K2L" 0603 -64.739,-21.283 r270 top value=40.2k
R28 "CRCW06031K00FKEA" 0603 -54.355,-27.979 r0 top value=1.00k
R29 "CRCW0603332KFKEA" 0603 -63.215,-25.735 r90 top value=332k
R30 "CRCW060310K0FKEA" 0603 -40.072,-25.27 r0 bottom value=10.0k
R31 "FC0603E50R0BTBST1" 0603 -54.38,-31.036 r0 top value=50
R32 "KRL2012E-M-R004-F-T5" FP-KRL2012E-M-R004-F-T5_2012-MFG -14.122,-37.671 r0 top value=4m
R33 "RT0603DRE0754K2L" 0603 -26.308,-13.758 r0 top value=54.2k
R34 "RT0603BRD0710KL" 0603 -29.582,-13.758 r180 top value=10.0k
R35 "RT0603BRD0710KL" 0603 -12.538,-13.062 r180 top value=10.0k
R36 "RT0603DRE0754K2L" 0603 -30.721,-60.51 r0 top value=54.2k
R37 "FC0603E50R0BTBST1" 0603 -12.538,-11.509 r180 top value=50
R38 "RT0603BRD0710KL" 0603 -12.538,-9.733 r180 top value=10.0k
R39 "RT0603BRD0710KL" 0603 -33.995,-60.51 r180 top value=10.0k
R40 "RC0603FR-072K21L" 0603 -12.538,-8.256 r180 top value=2.21k
R41 "RT0603BRD0710KL" 0603 -28.315,-43.79 r270 top value=10.0k
R42 "RT0603BRD0790K9L" 0603 -26.233,-9.28 r0 top value=90.9k
R43 "RT0603BRD07271KL" 0603 -31.255,-58.067 r270 top value=271k
R44 "RT0603BRD0742K2L" 0603 -12.538,-5.289 r0 top value=42.2k
R45 "RT0603BRD07511KL" 0603 -12.613,-11.677 r180 bottom value=511k
R46 "CRCW060349K9FKEA" 0603_HV -67.734,-61.459 r270 top value=49.9k
R47 "CRCW060375K0FKEA" 0603_HV -66.88,-69.031 r0 top value=75.0k
R48 "CRCW060324K9FKEA" 0603_HV -66.88,-70.555 r0 top value=24.9k
R49 "CRCW0603100KFKEA" 0603_HV -63.451,-64.459 r90 top value=100k
R50 "CRCW060310K0FKEA" 0603_HV -61.927,-64.459 r90 top value=10.0k
R51 "CRCW06033R01FKEA" 0603_HV -53.799,-58.363 r90 top value=3.01
R52 "CRCW06032K87FKEA" 0603_HV -63.451,-67.507 r90 top value=2.87k
R53 "CRCW06033K24FKEA" 0603_HV -61.927,-67.507 r90 top value=3.24k
R54 "CRCW12061K00JNEA" 1206 -70.094,-42.739 r0 top value=1.0k
R55 "CRCW06033R01FKEA" 0603_HV -55.323,-58.363 r90 top value=3.01
R56 "CRCW060310K0FKEA" 0603_HV -51.518,-57.652 r180 top value=10.0k
R57 "CRCW06031K00FKEA" 0603_HV -49.725,-60.216 r270 top value=1.00k
R58 "CSR0805FKR250" FP-CSR0805FKR250_0805-MFG -49.735,-55.696 r180 top
R59 "RC1210JR-071KL" 1210 -59.514,-55.569 r270 top value=1.0k
R60 "CRCW12062K20JNEA" 1206 -74.031,-49.851 r0 top value=2.2k
R61 "CRCW06037K87FKEA" 0603_HV -50.515,-65.437 r180 top value=7.87k
R62 "CRCW0603118KFKEA" 0603_HV -50.505,-70 r270 top value=118k
R63 "CRCW0603499KFKEA" 0603_HV -58.676,-70 r90 top value=499k
R64 "CRCW0603205KFKEA" 0603_HV -57.299,-70 r90 top value=205k
R65 "CRCW060349K9FKEA" 0603_HV -50.515,-66.879 r180 top value=49.9k
R66 "CRCW06036K19FKEA" 0603_HV -51.819,-70 r90 top value=6.19k
R67 "FC0603E50R0BTBST1" 0603 -31.103,-41.365 r180 top value=50
R68 "RT0603BRD0710KL" 0603 -31.786,-43.79 r90 top value=10.0k
R69 "RT0603BRD0710KL" 0603 -29.636,-58.064 r90 top value=10.0k
R70 "RC0603FR-071K37L" 0603 -30.28,-43.79 r270 top value=1.37k
R71 "ERJ-3EKF4531V" 0603 -54.355,-29.565 r0 top value=4.53k
R72 "RT0603BRD0790K9L" 0603 -35.327,-58.122 r90 top value=90.9k
R73 "RG1608P-203-B-T5" 0603 -62.361,-28.392 r0 top value=20.0k
R74 "RT0603BRD0765K7L" 0603 -34.803,-43.79 r90 top value=65.7k
R75 "CRCW0603430KJNEA" 0603 -30.971,-43.726 r270 bottom value=430k
R76 "CRCW060349K9FKEA" 0603_HV -127.967,-32.517 r0 top value=49.9k
R77 "CRCW06030000Z0EA" 0603_HV -75.927,-38.136 r180 top value=0
R78 "CRCW06030000Z0EA" 0603_HV -66.386,-56.065 r0 top value=0
R79 "RT0603BRD0710KL" 0603 -47.442,-18.516 r270 top value=10.0k
R80 "CRCW060310K0FKEA" 0603 -40.086,-27.499 r180 bottom value=10.0k
R81 "CRCW06030000Z0EA" 0603_HV -52.113,-32.376 r270 bottom value=0
R82 "CRCW06030000Z0EA" 0603_HV -50.081,-32.376 r270 bottom value=0
R83 "RC0603FR-07120RL" 0603 -49.911,-28.232 r90 bottom value=120
R84 "RC0603FR-07120RL" 0603 -51.522,-28.232 r90 bottom value=120
R101 "CRCW0603147KFKEA" 0603_HV -129.455,-39.648 r90 top value=147k
R102 "CRCW060375K0FKEA" 0603_HV -127.931,-39.648 r90 top value=75.0k
R103 "CRCW12061R69FKEA" 1206 -141.7,-72.283 r180 top value=1.69
R104 "CRCW060349K9FKEA" 0603_HV -127.967,-37.137 r0 top value=49.9k
R105 "RC0603FR-07205KL" 0603_HV -130.979,-39.648 r270 top value=205k
R106 "CRCW06031M00JNEA" 0603_HV -127.967,-34.089 r180 top value=1.0Meg
R107 "CRCW06030000Z0EA" 0603_HV -127.18,-30.36 r270 top value=0
R109 "CRCW06030000Z0EA" 0603_HV -140.758,-33.679 r180 top value=0
R110 "CRCW060334K8FKEA" 0603_HV -140.758,-36.727 r180 top value=34.8k
R111 "CRCW06031K50FKEA" 0603_HV -140.758,-30.631 r180 top value=1.50k
R112 "CRCW060330K1FKEA" 0603_HV -134.027,-39.648 r270 top value=30.1k
R113 "CRCW0603100RJNEA" 0603_HV -134.993,-24.808 r180 top value=100
R114 "CRCW0603100RJNEA" 0603_HV -137.965,-25.899 r270 top value=100
R115 "RC0805JR-070RL" 0805_HV1 -140.378,-49.724 r90 top value=0
R116 "RC0805JR-070RL" 0805_HV1 -75.781,-40.819 r90 top value=0
R117 "CRCW251233R0JNEG" 2512 -122.725,-33.722 r0 top value=33
R118 "CRCW251233R0JNEG" 2512 -114.851,-6.354 r270 top value=33
R119 "CRCW251233R0JNEG" 2512 -121.328,-37.659 r0 top value=33
R120 "CRCW251233R0JNEG" 2512 -111.112,-6.354 r270 top value=33
R121 "CRM2512-FX-1002ELF" FP-CRM2512-FX-1002ELF_2512-MFG -93.375,-5.263 r0 top value=10k
R122 "CRCW060310K0FKEA" 0603_HV -137.025,-50.613 r180 top value=10.0k
R123 "CRCW060310K0FKEA" 0603_HV -80.387,-51.768 r0 top value=10.0k
R124 "CRCW060310R0FKEA" 0603_HV -140.759,-44.695 r90 top value=10.0
R125 "CRCW0603115KFKEA" 0603_HV -137.075,-39.648 r270 top value=115k
R126 "CRCW06036K19FKEA" 0603_HV -138.599,-39.648 r90 top value=6.19k
R201 "CRCW06030000Z0EA" 0603_HV -133.655,-48.723 r0 top value=0
R202 "CRCW06030000Z0EA" 0603_HV -134.344,-55.245 r270 top value=0
R203 "CRCW0603100KFKEA" 0603_HV -131.393,-55.245 r270 top value=100k
R204 "CRCW0603100RJNEA" 0603_HV -132.162,-58.206 r180 top value=100
R205 "CRCW0603100KFKEA" 0603_HV -134.344,-51.383 r270 top value=100k
R206 "CRCW060310K0FKEA" 0603_HV -132.9,-55.245 r90 top value=10.0k
R207 "MCT06030C2008FP500" 0603_HV -133.655,-47.3 r180 top value=2.00
R208 "CRCW06032R49FKEA" 0603_HV -119.38,-47.871 r180 top value=2.49
R209 "CRCW06032R49FKEA" 0603_HV -119.38,-46.271 r180 top value=2.49
R210 "CRCW06032R49FKEA" 0603_HV -119.353,-55.41 r180 top value=2.49
R211 "CRCW06032R49FKEA" 0603_HV -119.353,-53.915 r180 top value=2.49
R212 "CRCW060310K0FKEA" 0603_HV -118.603,-50.121 r270 top value=10.0k
R213 "CRCW060310K0FKEA" 0603_HV -118.564,-57.621 r270 top value=10.0k
R214 "CRCW06030000Z0EA" 0603_HV -79.148,-69.698 r90 top value=0
R215 "CRCW0603100KFKEA" 0603_HV -80.545,-63.119 r90 top value=100k
R216 "CRCW06030000Z0EA" 0603_HV -77.538,-63.119 r90 top value=0
R217 "CRCW0603100RJNEA" 0603_HV -79.546,-58.499 r180 top value=100
R218 "CRCW0603100KFKEA" 0603_HV -77.56,-66.338 r90 top value=100k
R219 "CRCW060310K0FKEA" 0603_HV -78.97,-63.119 r270 top value=10.0k
R220 "MCT06030C2008FP500" 0603_HV -77.522,-69.698 r270 top value=2.00
R221 "CRCW06032R49FKEA" 0603_HV -92.734,-70.4 r0 top value=2.49
R222 "CRCW06032R49FKEA" 0603_HV -92.734,-71.948 r0 top value=2.49
R223 "CRCW06032R49FKEA" 0603_HV -92.734,-62.908 r0 top value=2.49
R224 "CRCW06032R49FKEA" 0603_HV -92.734,-64.408 r0 top value=2.49
R225 "CRCW060310K0FKEA" 0603_HV -93.485,-68.158 r90 top value=10.0k
R226 "CRCW060310K0FKEA" 0603_HV -93.485,-60.658 r90 top value=10.0k
R227 "CRCW06030000Z0EA" 0603_HV -140.478,-11.984 r0 top value=0
R228 "CRCW060310K0FKEA" 0603_HV -140.478,-19.579 r180 top value=10.0k
R229 "CRCW06030000Z0EA" 0603_HV -140.478,-18.055 r0 top value=0
R230 "CRCW060349K9FKEA" 0603_HV -140.478,-16.531 r180 top value=49.9k
R231 "CRCW06032R49FKEA" 0603_HV -126.929,-11.828 r180 top value=2.49
R232 "CRCW06032R49FKEA" 0603_HV -126.908,-10.304 r180 top value=2.49
R233 "CRCW06032R49FKEA" 0603_HV -126.9,-19.354 r180 top value=2.49
R234 "CRCW06032R49FKEA" 0603_HV -126.9,-17.905 r180 top value=2.49
R235 "CRCW060310K0FKEA" 0603_HV -126.183,-14.054 r270 top value=10.0k
R236 "CRCW060310K0FKEA" 0603_HV -126.183,-21.554 r270 top value=10.0k
R237 "CRCW06030000Z0EA" 0603_HV -140.049,-21.658 r0 top value=0
R238 "CRCW06030000Z0EA" 0603_HV -140.049,-22.913 r0 top value=0
R301 "CRM2512-FX-1002ELF" FP-CRM2512-FX-1002ELF_2512-MFG -93.375,-9.349 r0 top value=10k
SGND "SGND_2" Keystone5011 -143.553,-63.694 r0 top
SGND_1 "5011" Keystone5011 -33.702,-3.725 r270 top
SGND_3 "SGND_3" Keystone5011 -5.885,-41.977 r180 top
T1 "CP-D1551-BZ" FP-CP-D1551-BZ_SMT_XFRMR_17MM75_14MM0-MFG -58.781,-42.272 r90 top
T2 "CM3440Z171R-10" Laird_Z171R-10 -15.758,-78.102 r180 top
T102 "63554-R01" FP-63554-R01_SMT_XFRMR_24MM0_20MM0-MFG -124.415,-72.076 r180 top
T103 "CP-D1549-BZ" FP-CP-D1549-BZ_SMT_XFRMR_29MM46_26MM67-MFG -103.337,-26.403 r90 top
U1 "MSP430FR5969IRGZR" RGZ0048B -81.468,-27.853 r270 top
U2 "OPA4H199MDYYTSEP" DYY0014A-MFG -44.469,-25.805 r90 top
U3 "TMP9R01MDGSTSEP" DGS0010A-MFG -81.314,-33.813 r0 top
U4 "TPS7H4013MDDWTSEP" DDW0044F-MFG -19.454,-14.575 r0 top
U5 "TL1431U/EM" NAC0010A-IPC_B -72.557,-63.661 r270 top
U6 "TPS7H5020MPWPTSEP" PWP0024R-MFG -56.499,-63.543 r270 top
U7 "TPS7H4011MDDWTSEP" DDW0044F-MFG -28.048,-50.924 r90 top
U8 "TPS7H1121MPWPTSEP" PWP0024R-MFG -58.406,-23.213 r0 top
U9 "THVD1452D" D0014A_N -45.534,-26.964 r180 bottom
U101 "TPS7H5005MPWSEP" PW0024A-MFG -134.281,-33.806 r180 top
U201 "TPS7H6005/EM" DCA0056M-MFG -125.515,-52.609 r0 top
U202 "TPS7H6005/EM" DCA0056M-MFG -86.483,-65.678 r180 top
U203 "TPS7H6005/EM" DCA0056M-MFG -133.183,-16.554 r0 top
UART/D "PTT-103-01-L-S" Samtec_PTT-103-01-x-S -143.553,-27.372 r270 top
UART/R "PTT-103-01-L-S" Samtec_PTT-103-01-x-S -143.553,-35.373 r270 top
VIN_28V "5010" Keystone5010 -65.353,-76.45 r270 top
Y1 "MS3V-T1R 32.768KHZ 7.0 PF" XTAL_MS3V-T1R -72.179,-27.245 r0 top

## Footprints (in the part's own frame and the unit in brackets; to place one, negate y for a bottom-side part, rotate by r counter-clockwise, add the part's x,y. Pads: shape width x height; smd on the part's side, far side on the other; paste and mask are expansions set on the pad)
0402 [mm] "0402 from SM-752 data"
  rect 0.8x0.6 smd: 1(-0.6,0) 2(0.6,0)
  silkscreen extent -1.22,-0.52 1.22,0.52, body extent -0.55,-0.3 0.55,0.3, height 0.6
0603 [mm] "0603 from SM-752 data"
  rect 1x0.95 smd: 1(-0.8,0) 2(0.8,0)
  silkscreen extent -1.52,-0.69 1.52,0.69, body extent -0.87,-0.47 0.87,0.47, height 1
0603_HV [mil] "Ernesto recommended land pattern.  26 mil between pads."
  rect 30x30 smd: 1(-28,0) 2(28,0)
  silkscreen extent -52,-24 52,24, body extent -34,-19 34,19, height 39
0603L [mm] "0603 from SM-752 data"
  rect 0.8x0.85 smd: 1(-0.7,0) 2(0.7,0)
  silkscreen extent -0.07,-0.32 0.07,0.32, body extent -0.87,-0.47 0.87,0.47, height 1
0805 [mm] "0805 from SM-752 data"
  rect 1.3x1.5 smd: 1(-0.85,0) 2(0.85,0)
  silkscreen extent -1.72,-0.97 1.72,0.97, body extent -1.1,-0.72 1.1,0.72, height 1.45
0805_HV [mil] "0805 with 30mil clearance between pads"
  rect 50x63 smd: 1(-40,0) 2(40,0)
  silkscreen extent -74,-40 74,40, body extent -43,-29 43,29, height 57
0805_HV1 [mm] "Custom footprint based on analyzing multiple manufacturer recommendations"
  rrect10% 1x1.25 smd: 1(-1,0) 2(1,0)
  silkscreen extent -0.2,-0.75 0.2,0.75, body extent -1.1,-0.72 1.1,0.73, height 1.45
0805L [mm] "0805 from SM-752 data"
  rect 1.1x1.4 smd: 1(-0.75,0) 2(0.75,0)
  body extent -1.1,-0.72 1.1,0.72, height 1.45
1206 [mm] "1206 from SM-752 data"
  rect 1.3x1.85 smd: 1(-1.45,0) 2(1.45,0)
  silkscreen extent -2.4,-1.21 2.4,1.21, body extent -1.7,-0.9 1.7,0.9, height 1.35
1210 [mm] "1210 from SM-752 data"
  rect 1.3x2.7 smd: 1(-1.45,0) 2(1.45,0)
  silkscreen extent -2.32,-1.57 2.32,1.57, body extent -1.7,-1.35 1.7,1.35, height 1.35
1210_270 [mm] "1210"
  rect 1.3x2.7 smd: 1(-1.45,0) 2(1.45,0)
  silkscreen extent -2.32,-1.57 2.32,1.57, body extent -1.7,-1.35 1.7,1.35, height 2.7
2512 [mm] "Chip Resistor, Body 6.3x3.2mm, IPC Medium Density"
  rect 1.3x3.4 smd: 1(-2.95,0) 2(2.95,0)
  silkscreen extent -1.9,-1.6 1.9,1.6, body extent -3.22,-1.67 3.22,1.67, height 0.71
7343-43 [mm] "Medium density IPC based on Kemet T495 series"
  rect 2.55x2.45 smd: 1(-3.025,0) 2(3.025,0)
  silkscreen extent -4.56,-2.3 3.8,2.3, body extent -3.8,-2.3 3.8,2.3, height 4.3
7361-38 [mm] "Medium density IPC based on AVX dimensions for TPS series"
  rect 2.55x3.2 smd: 1(-2.975,0) 2(2.975,0)
  silkscreen extent -4.51,-3.2 3.75,3.2, body extent -3.75,-3.15 3.75,3.15, height 3.8
CONN_SBH11-PBPC-D07-ST-BK [mm] "Sullins recommended land pattern"
  rect 1.65x1.65 hole 1.016 mask+0: 1(-7.62,-1.27)
  round 1.65 hole 1.016 mask+0: 2(-7.62,1.27) 3(-5.08,-1.27) 4(-5.08,1.27) 5(-2.54,-1.27) 6(-2.54,1.27) 7(0,-1.27) 8(0,1.27) 9(2.54,-1.27) 10(2.54,1.27) 11(5.08,-1.27) 12(5.08,1.27) 13(7.62,-1.27) 14(7.62,1.27)
  silkscreen extent -12.64,-5.08 12.64,4.7, body extent -12.64,-4.4 12.64,4.7, height 9.12
D0014A_N [mm] "SOIC, 14-Leads, Body 8.7x3.9mm, Pitch 1.27mm, IPC Medium Density"
  oval 1.45x0.6 smd: 1(-2.725,3.81) 2(-2.725,2.54) 3(-2.725,1.27) 4(-2.725,0) 5(-2.725,-1.27) 6(-2.725,-2.54) 7(-2.725,-3.81) 8(2.725,-3.81) 9(2.725,-2.54) 10(2.725,-1.27) 11(2.725,0) 12(2.725,1.27) 13(2.725,2.54) 14(2.725,3.81)
  silkscreen extent -3.3,-4.4 0.9,4.4, body extent -3.02,-4.32 3.02,4.32, height 1.6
